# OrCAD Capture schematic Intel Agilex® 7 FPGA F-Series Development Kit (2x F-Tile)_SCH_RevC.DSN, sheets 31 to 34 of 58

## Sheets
31 PG34 CXL CONNECTOR: size C
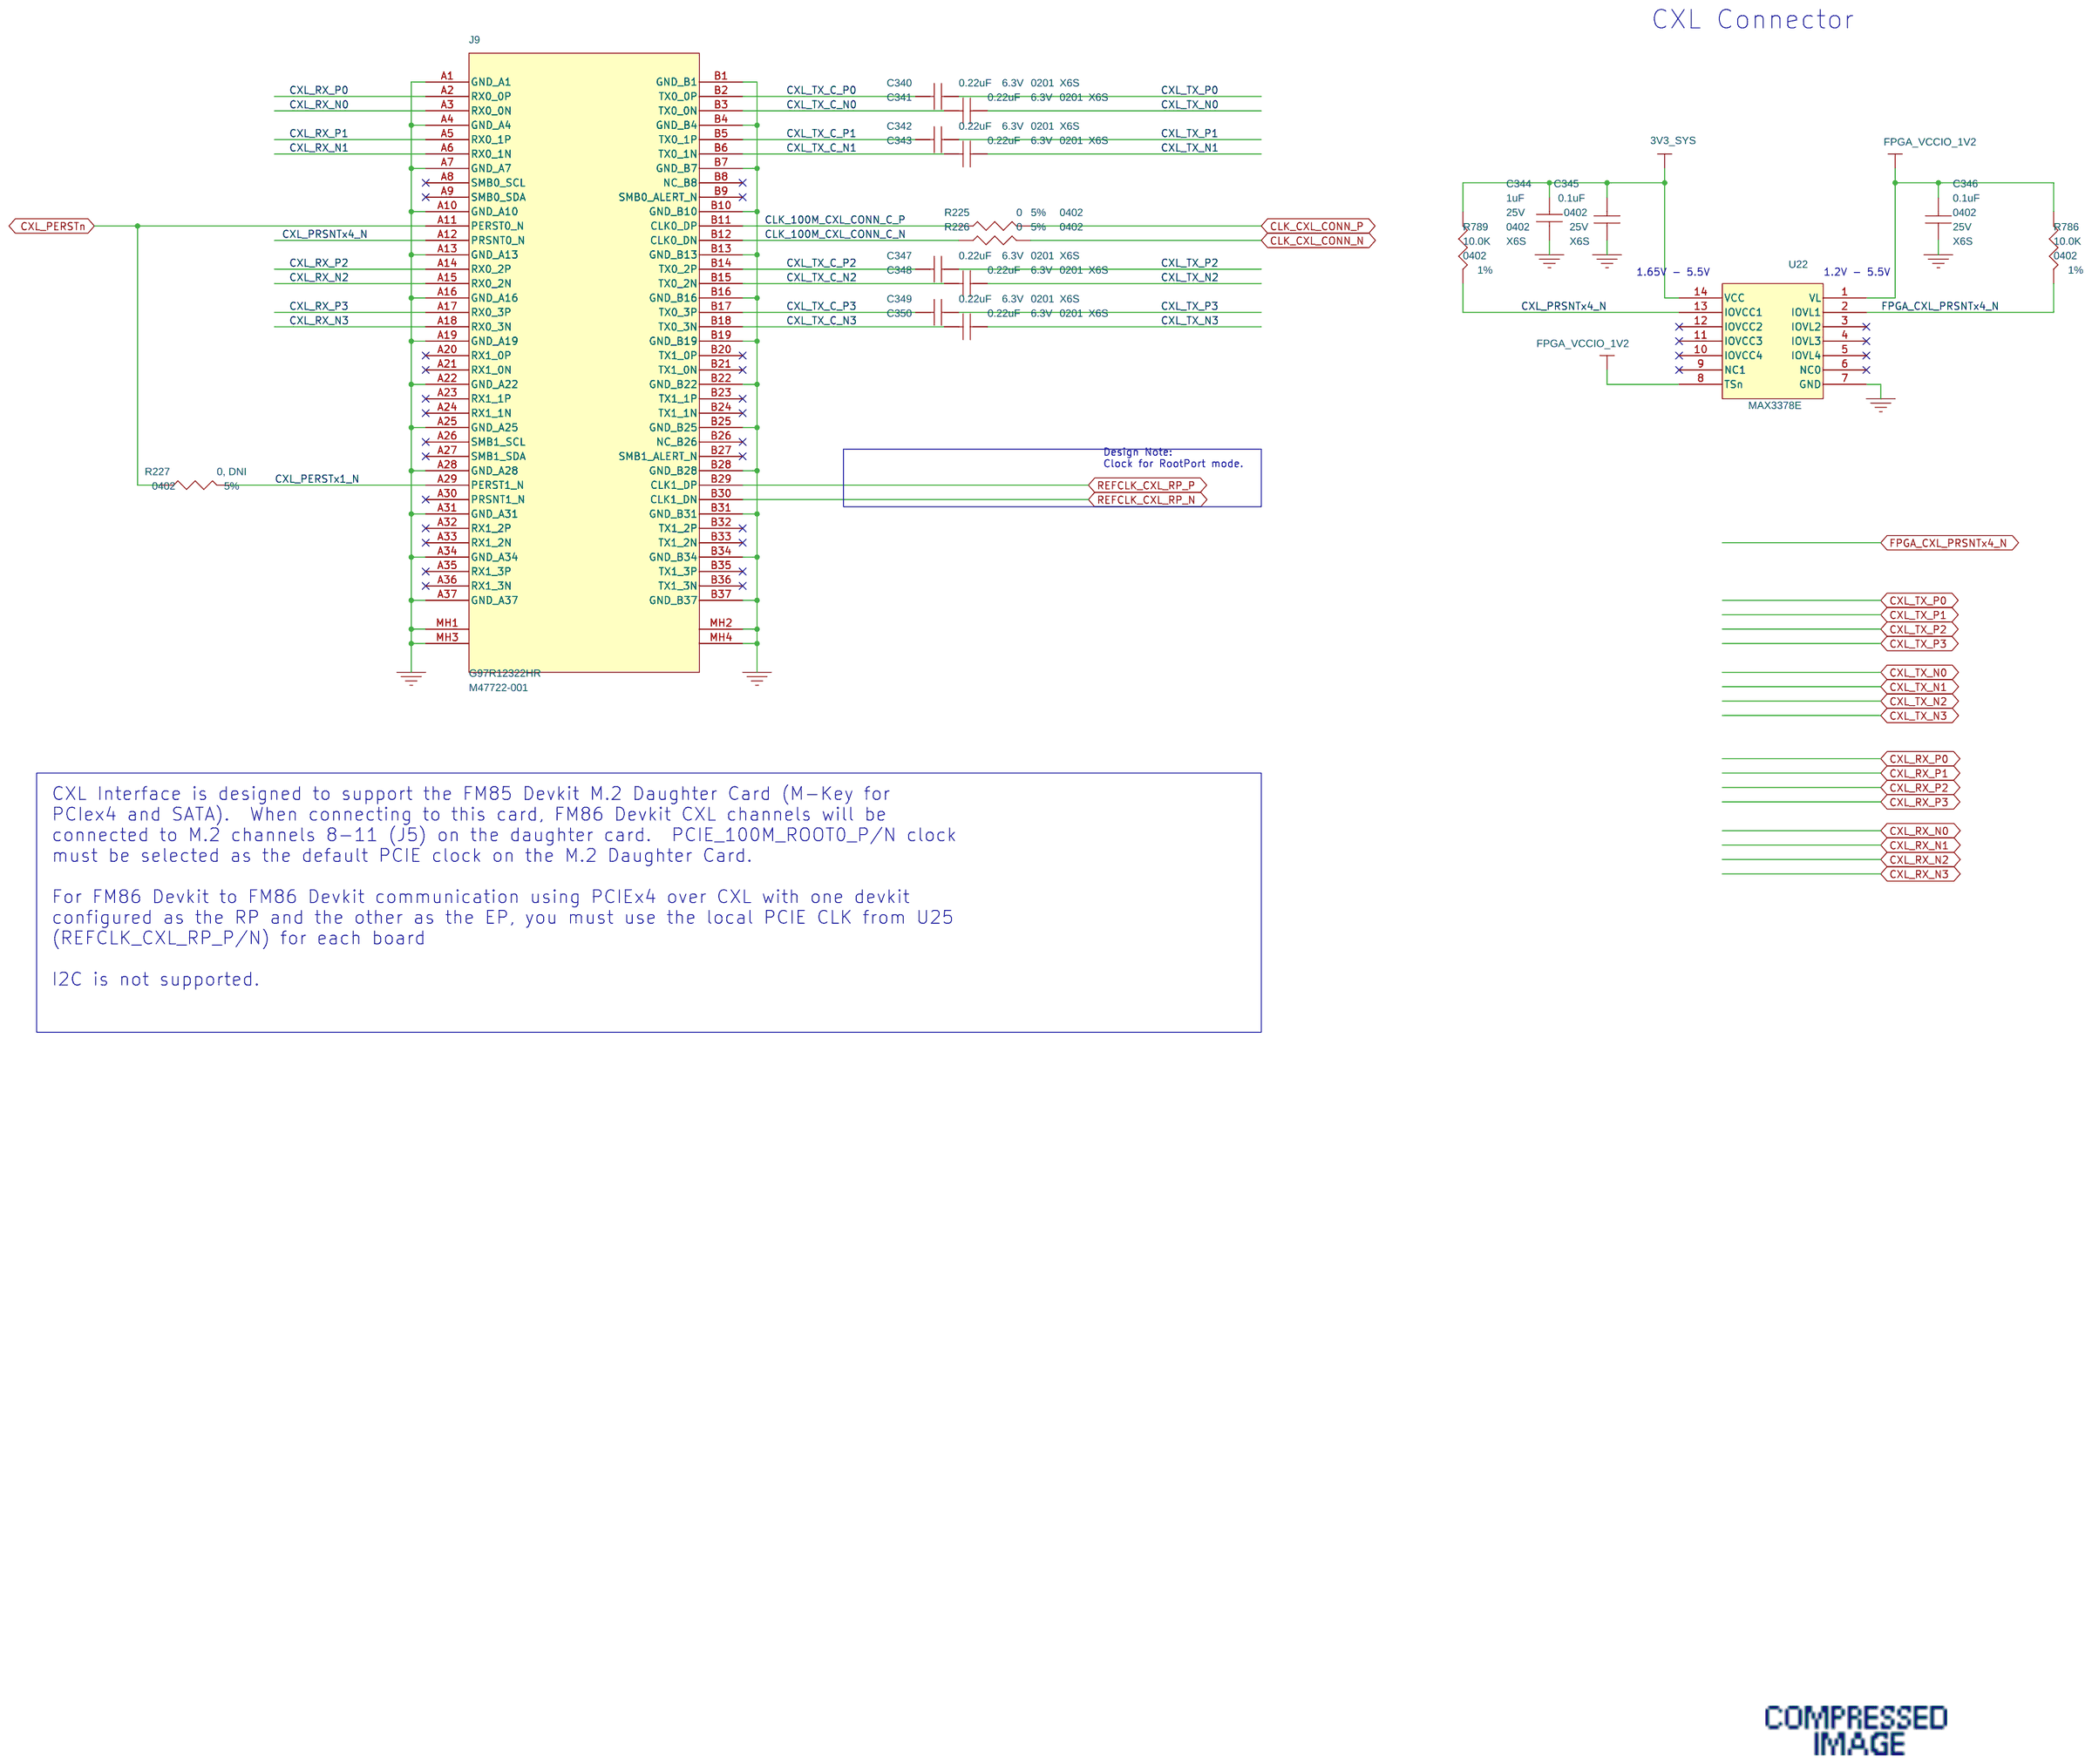
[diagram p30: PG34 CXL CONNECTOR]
32 PG35 CLOCK 1: size C
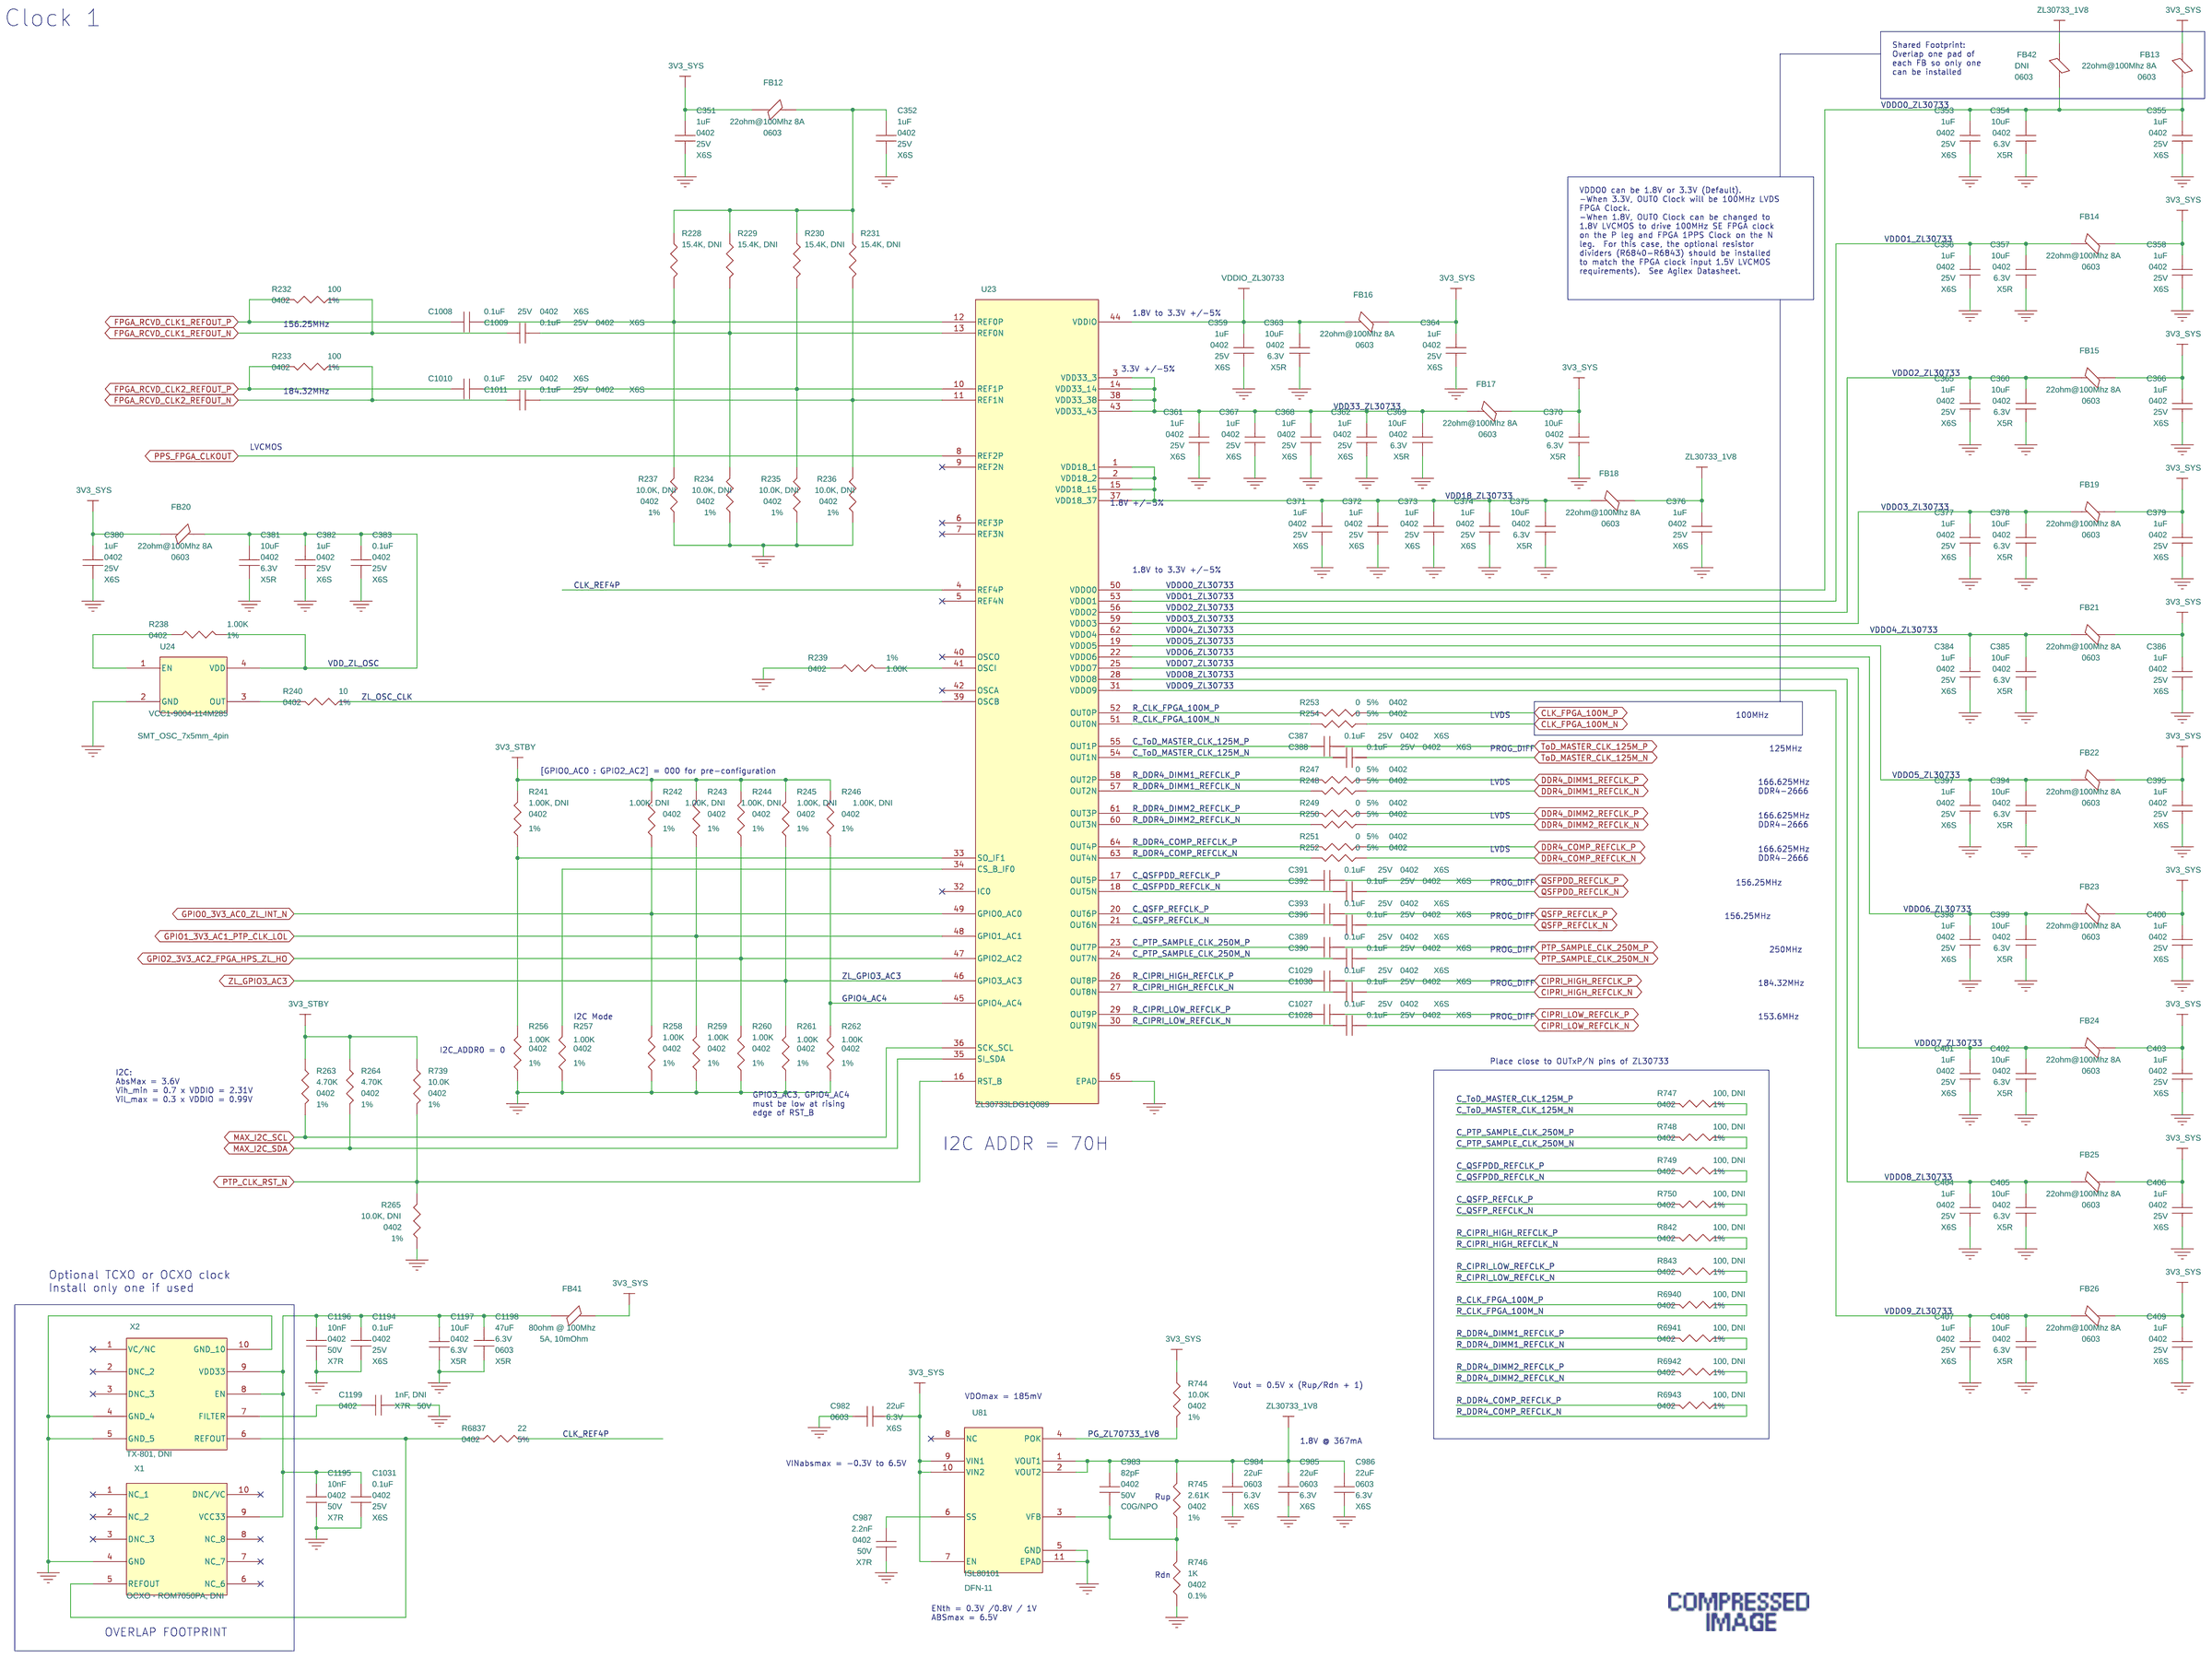
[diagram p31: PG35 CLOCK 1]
33 PG36 CLOCK 2: size C
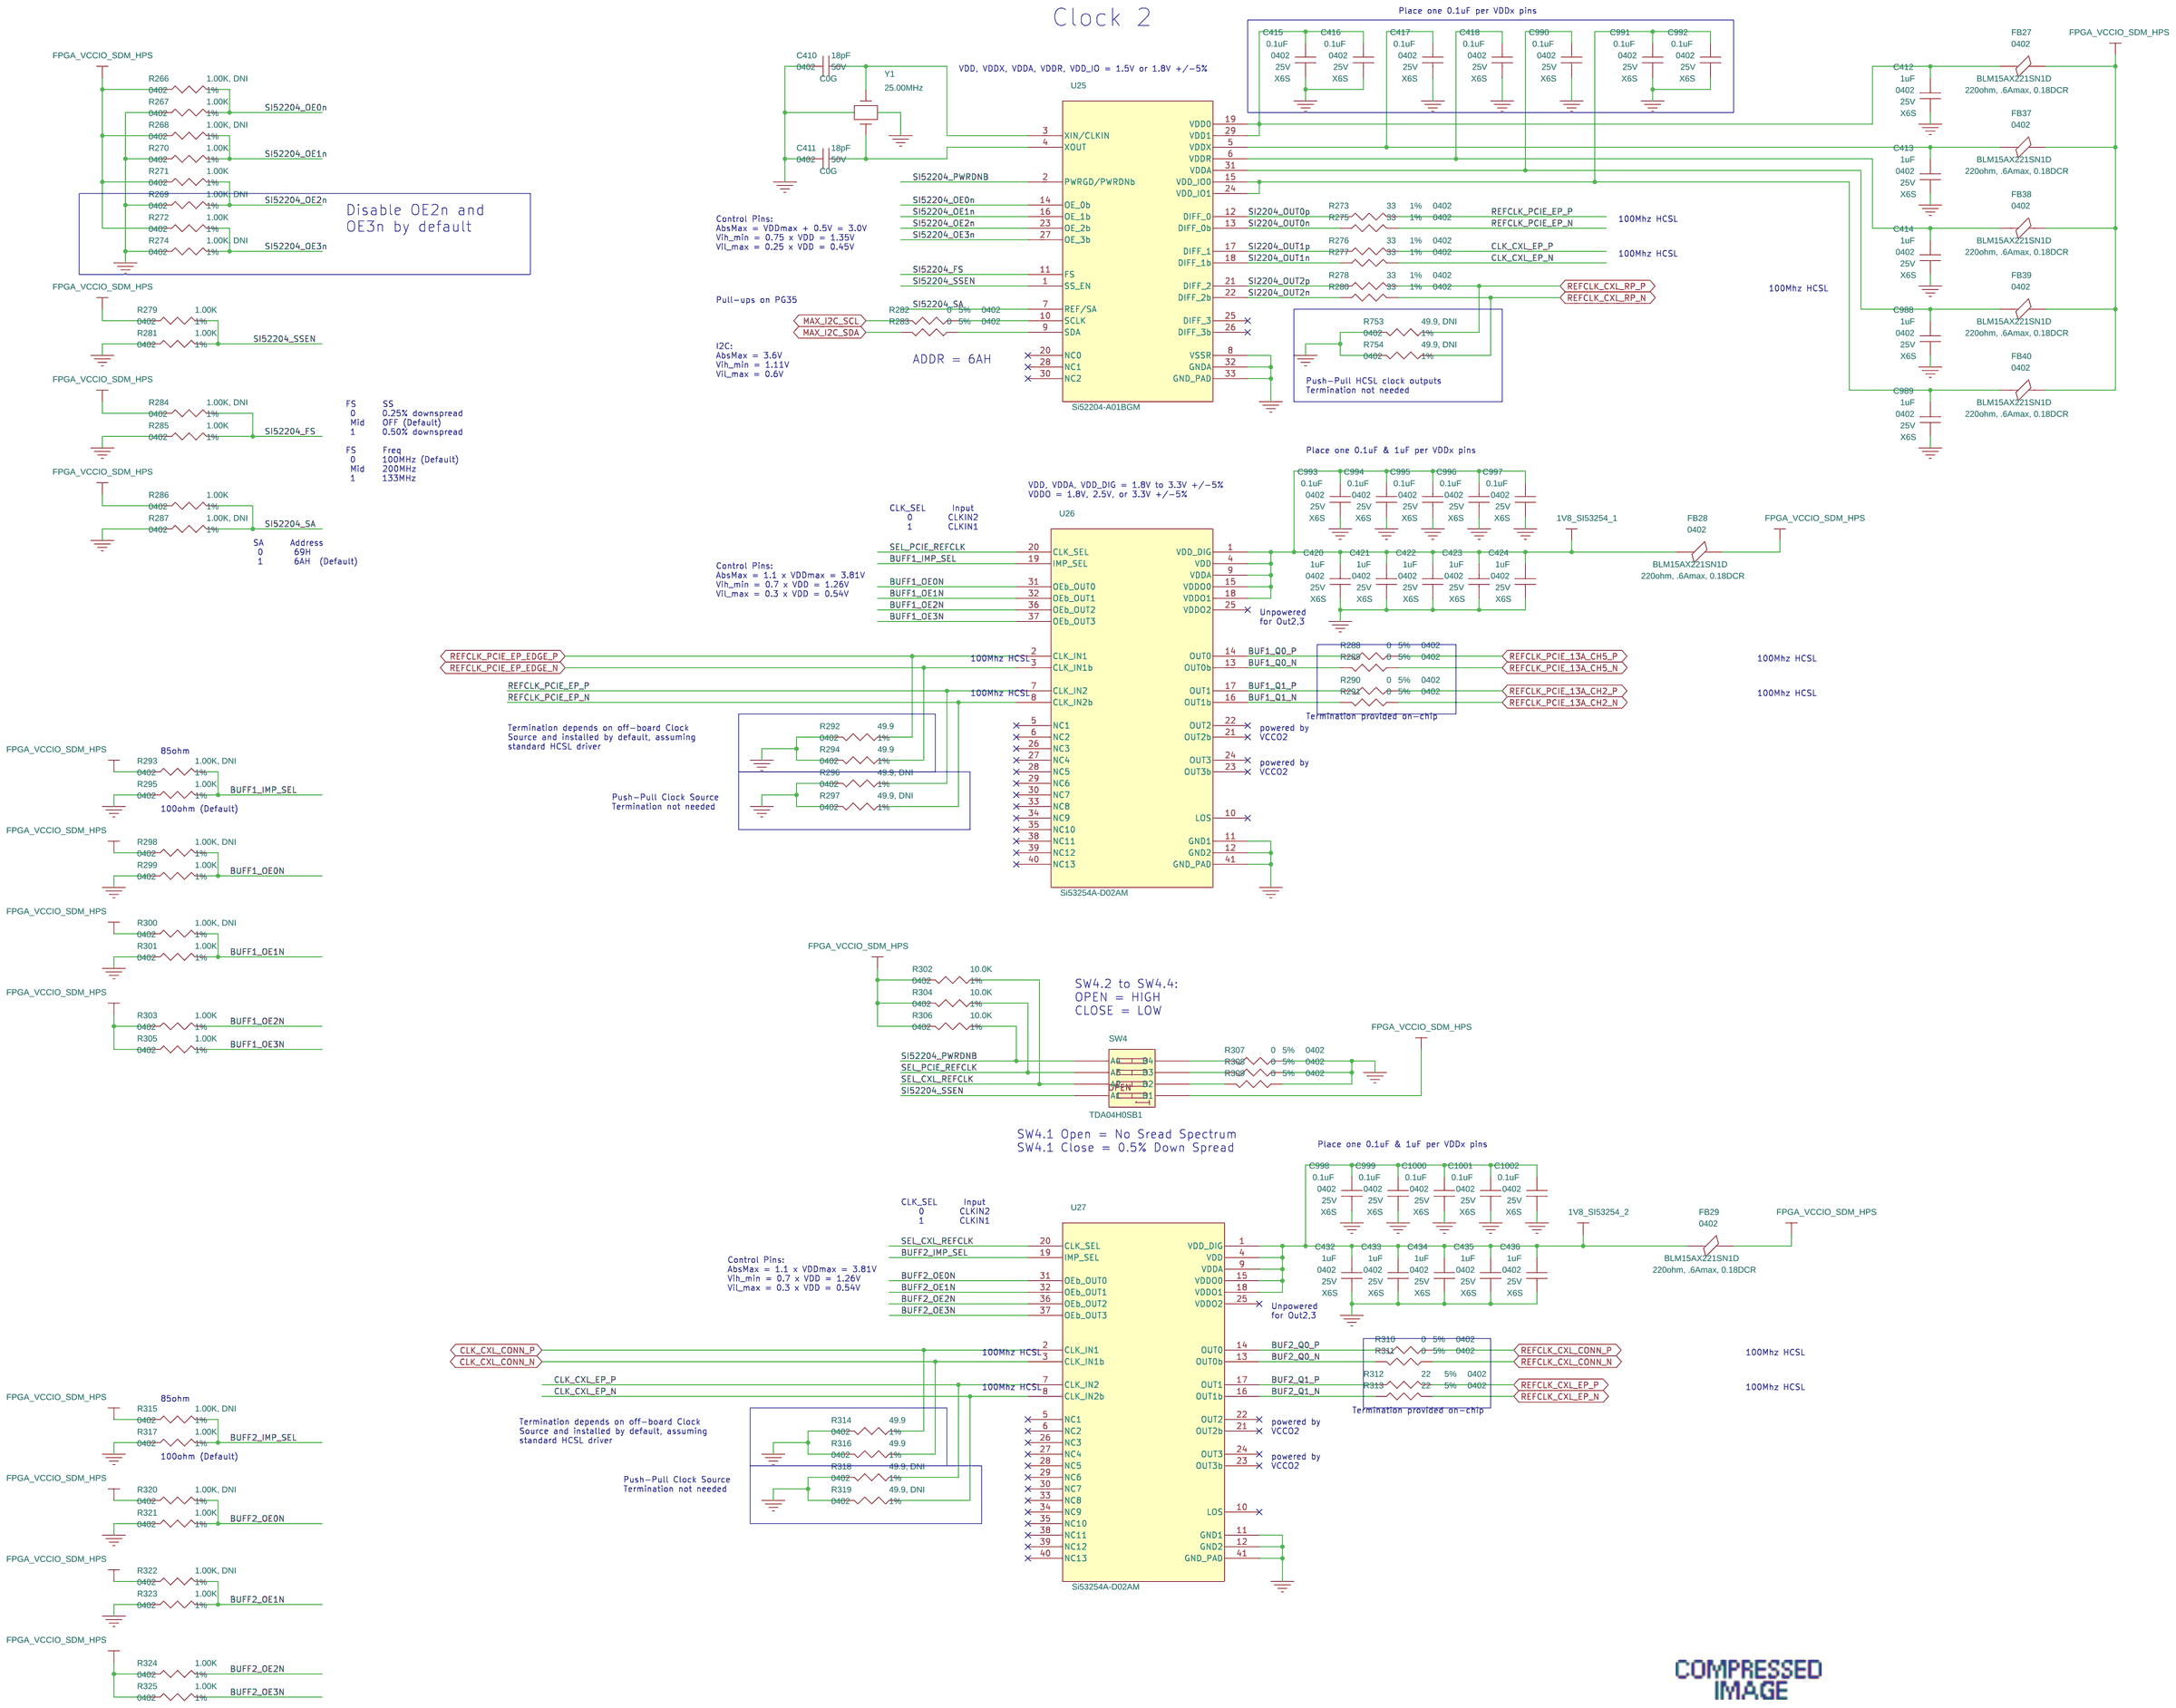
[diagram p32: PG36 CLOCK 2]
34 PG37 BUFFERS, TRANSLATORS: size C
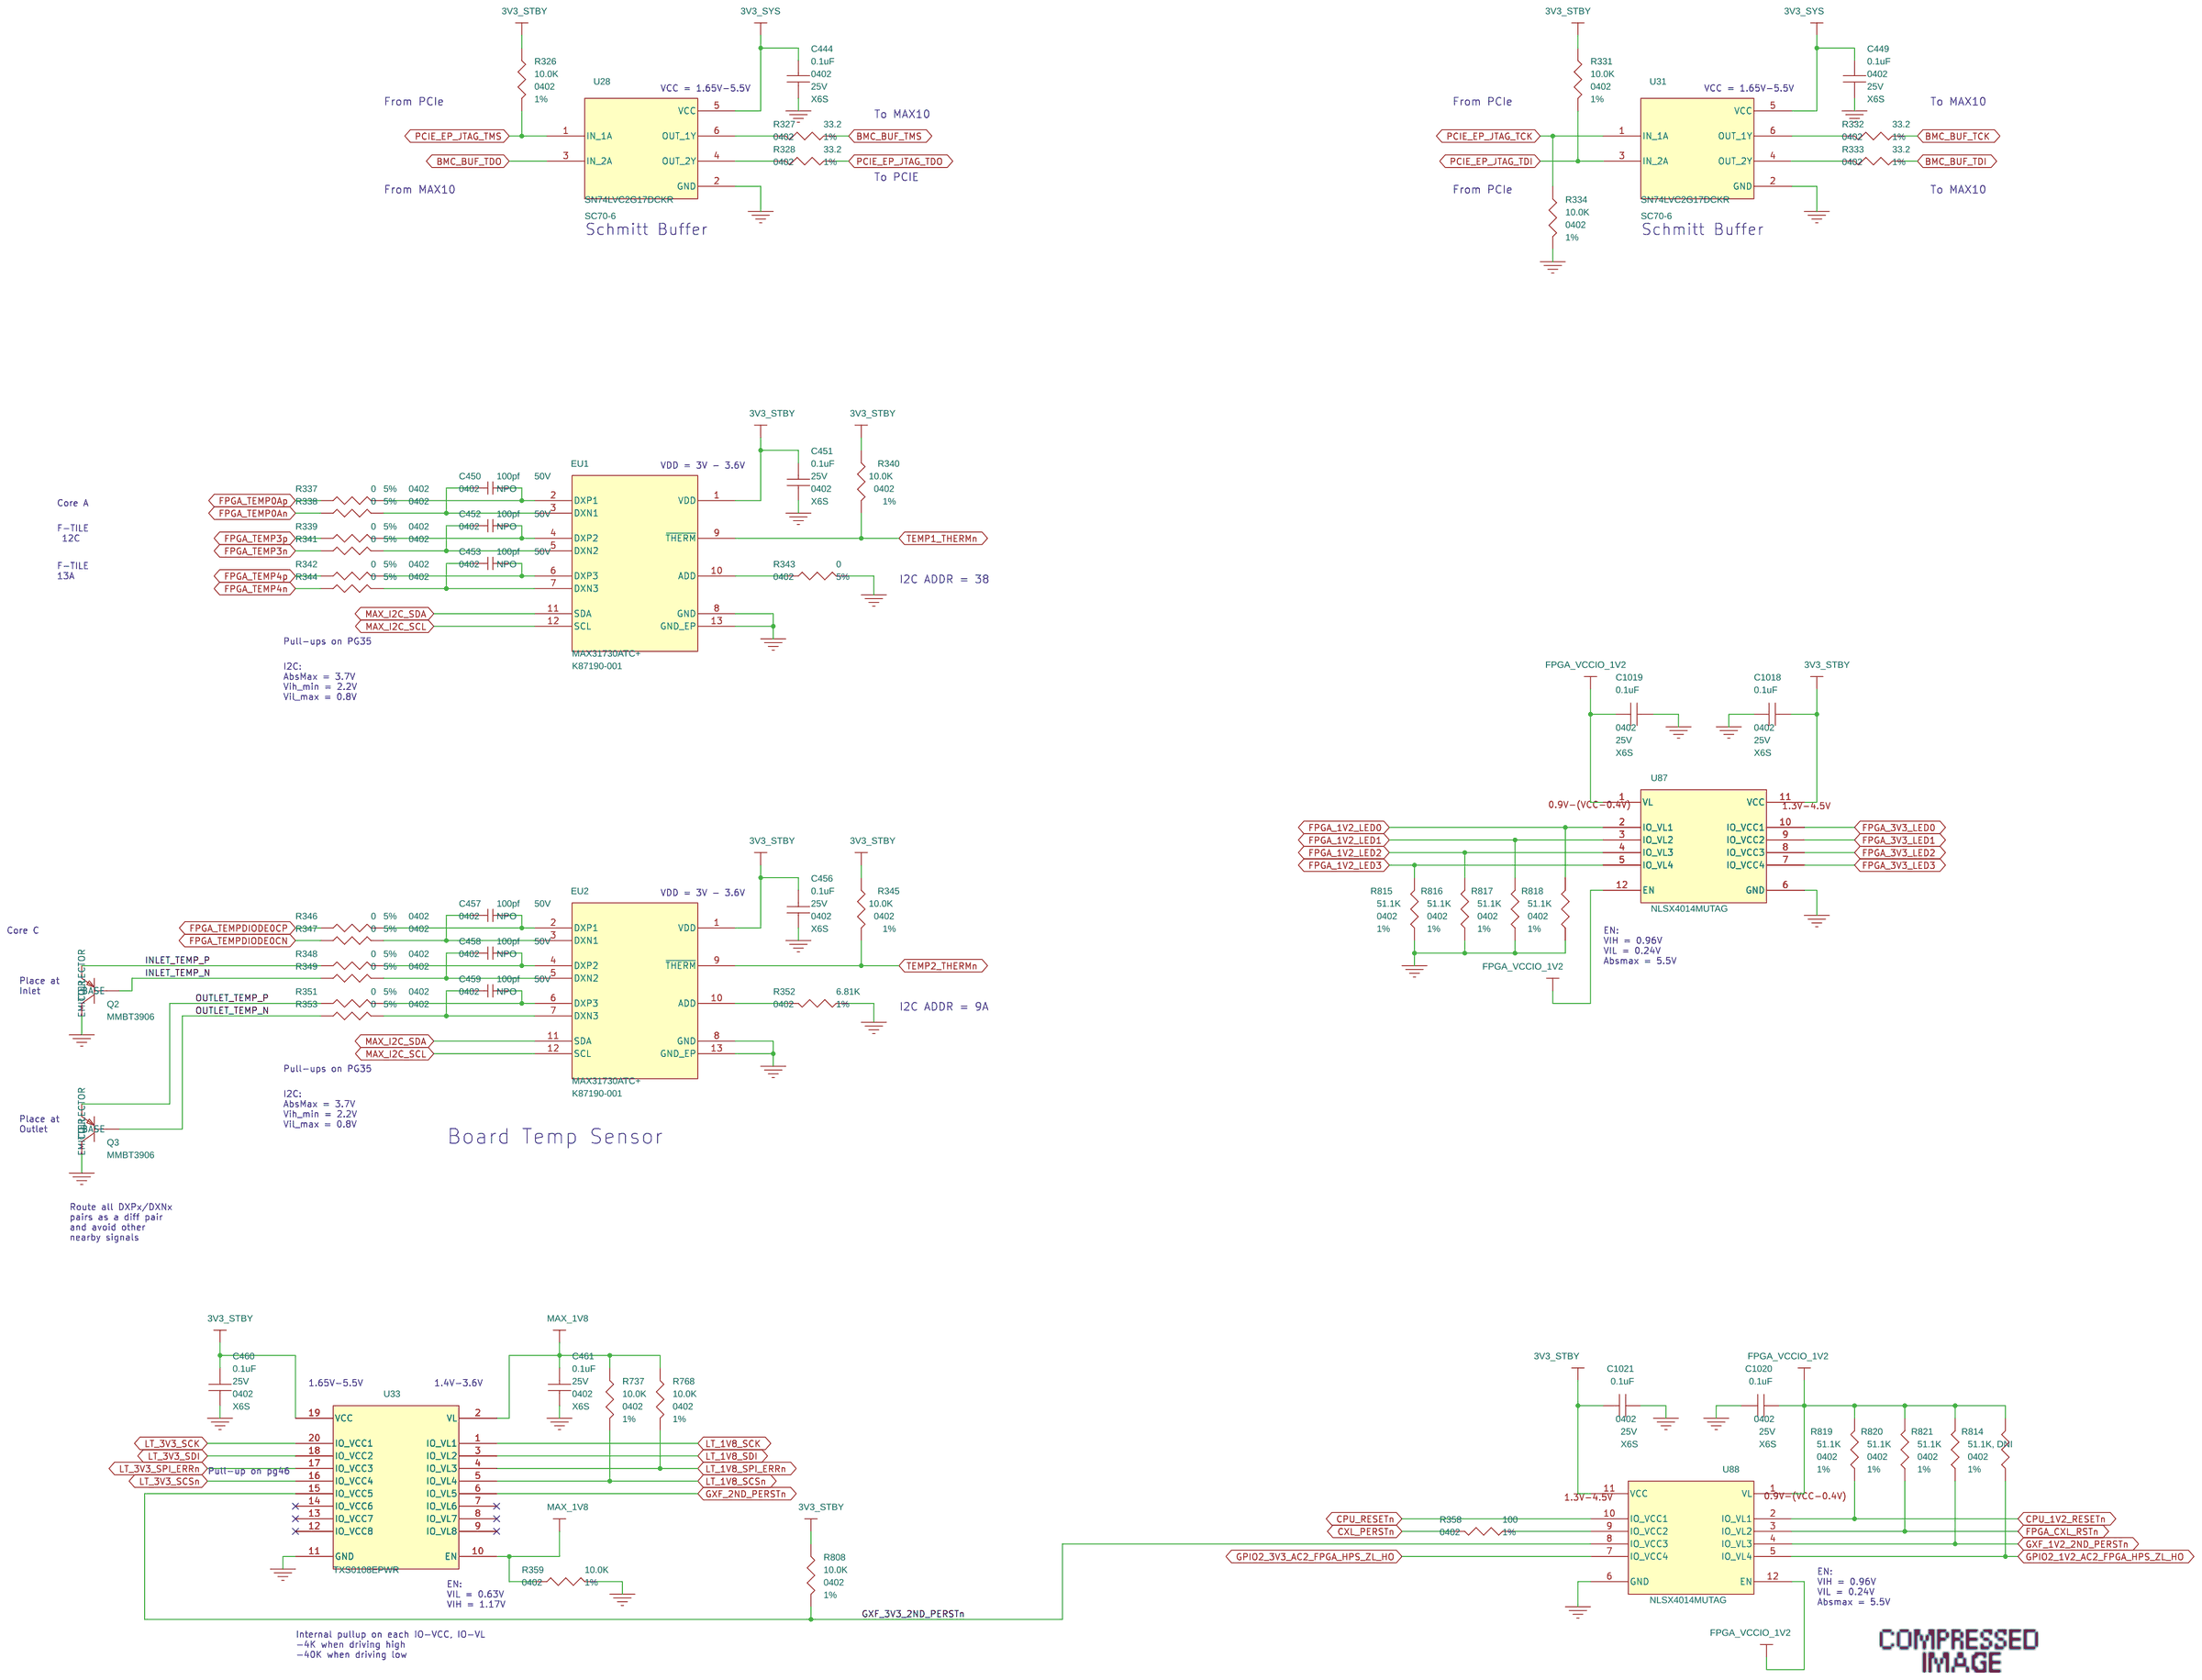
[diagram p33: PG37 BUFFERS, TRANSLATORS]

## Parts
sheet PG34 CXL CONNECTOR
C340  0.22uF  [SMC0201IA]
C341  0.22uF  [SMC0201IA]
C342  0.22uF  [SMC0201IA]
C343  0.22uF  [SMC0201IA]
C344  1uF  [0402]
C345  0.1uF  [0402]
C346  0.1uF  [0402]
C347  0.22uF  [SMC0201IA]
C348  0.22uF  [SMC0201IA]
C349  0.22uF  [SMC0201IA]
C350  0.22uF  [SMC0201IA]
J9  G97R12322HR  [G97R12322HR]
R225  0  [0402]
R226  0  [0402]
R227  0, DNI  [0402]
R786  10.0K  [0402]
R789  10.0K  [0402]
U22  MAX3378E  [TSSOP-14]
sheet PG35 CLOCK 1
C351  1uF  [0402]
C352  1uF  [0402]
C353  1uF  [0402]
C354  10uF  [0402]
C355  1uF  [0402]
C356  1uF  [0402]
C357  10uF  [0402]
C358  1uF  [0402]
C359  1uF  [0402]
C360  10uF  [0402]
C361  1uF  [0402]
C362  1uF  [0402]
C363  10uF  [0402]
C364  1uF  [0402]
C365  1uF  [0402]
C366  1uF  [0402]
C367  1uF  [0402]
C368  1uF  [0402]
C369  10uF  [0402]
C370  10uF  [0402]
C371  1uF  [0402]
C372  1uF  [0402]
C373  1uF  [0402]
C374  1uF  [0402]
C375  10uF  [0402]
C376  1uF  [0402]
C377  1uF  [0402]
C378  10uF  [0402]
C379  1uF  [0402]
C380  1uF  [0402]
C381  10uF  [0402]
C382  1uF  [0402]
C383  0.1uF  [0402]
C384  1uF  [0402]
C385  10uF  [0402]
C386  1uF  [0402]
C387  0.1uF  [0402]
C388  0.1uF  [0402]
C389  0.1uF  [0402]
C390  0.1uF  [0402]
C391  0.1uF  [0402]
C392  0.1uF  [0402]
C393  0.1uF  [0402]
C394  10uF  [0402]
C395  1uF  [0402]
C396  0.1uF  [0402]
C397  1uF  [0402]
C398  1uF  [0402]
C399  10uF  [0402]
C400  1uF  [0402]
C401  1uF  [0402]
C402  10uF  [0402]
C403  1uF  [0402]
C404  1uF  [0402]
C405  10uF  [0402]
C406  1uF  [0402]
C407  1uF  [0402]
C408  10uF  [0402]
C409  1uF  [0402]
C982  22uF  [0603]
C983  82pF  [0402]
C984  22uF  [0603]
C985  22uF  [0603]
C986  22uF  [0603]
C987  2.2nF  [0402]
C1008  0.1uF  [0402]
C1009  0.1uF  [0402]
C1010  0.1uF  [0402]
C1011  0.1uF  [0402]
C1027  0.1uF  [0402]
C1028  0.1uF  [0402]
C1029  0.1uF  [0402]
C1030  0.1uF  [0402]
C1031  0.1uF  [0402]
C1194  0.1uF  [0402]
C1195  10nF  [0402]
C1196  10nF  [0402]
C1197  10uF  [0402]
C1198  47uF  [0603]
C1199  1nF, DNI  [0402]
FB12  22ohm@100Mhz 8A  [0603]
FB13  22ohm@100Mhz 8A  [0603]
FB14  22ohm@100Mhz 8A  [0603]
FB15  22ohm@100Mhz 8A  [0603]
FB16  22ohm@100Mhz 8A  [0603]
FB17  22ohm@100Mhz 8A  [0603]
FB18  22ohm@100Mhz 8A  [0603]
FB19  22ohm@100Mhz 8A  [0603]
FB20  22ohm@100Mhz 8A  [0603]
FB21  22ohm@100Mhz 8A  [0603]
FB22  22ohm@100Mhz 8A  [0603]
FB23  22ohm@100Mhz 8A  [0603]
FB24  22ohm@100Mhz 8A  [0603]
FB25  22ohm@100Mhz 8A  [0603]
FB26  22ohm@100Mhz 8A  [0603]
FB41  80ohm @ 100Mhz  [0805]
FB42  DNI  [0603]
R228  15.4K, DNI  [HC_R0201]
R229  15.4K, DNI  [HC_R0201]
R230  15.4K, DNI  [HC_R0201]
R231  15.4K, DNI  [HC_R0201]
R232  100  [0402]
R233  100  [0402]
R234  10.0K, DNI  [0402]
R235  10.0K, DNI  [0402]
R236  10.0K, DNI  [0402]
R237  10.0K, DNI  [0402]
R238  1.00K  [0402]
R239  1.00K  [0402]
R240  10  [0402]
R241  1.00K, DNI  [0402]
R242  1.00K, DNI  [0402]
R243  1.00K, DNI  [0402]
R244  1.00K, DNI  [0402]
R245  1.00K, DNI  [0402]
R246  1.00K, DNI  [0402]
R247  0  [0402]
R248  0  [0402]
R249  0  [0402]
R250  0  [0402]
R251  0  [0402]
R252  0  [0402]
R253  0  [0402]
R254  0  [0402]
R256  1.00K  [0402]
R257  1.00K  [0402]
R258  1.00K  [0402]
R259  1.00K  [0402]
R260  1.00K  [0402]
R261  1.00K  [0402]
R262  1.00K  [0402]
R263  4.70K  [0402]
R264  4.70K  [0402]
R265  10.0K, DNI  [0402]
R739  10.0K  [0402]
R744  10.0K  [0402]
R745  2.61K  [0402]
R746  1K  [0402]
R747  100, DNI  [0402]
R748  100, DNI  [0402]
R749  100, DNI  [0402]
R750  100, DNI  [0402]
R842  100, DNI  [0402]
R843  100, DNI  [0402]
R6837  22  [0402]
R6940  100, DNI  [0402]
R6941  100, DNI  [0402]
R6942  100, DNI  [0402]
R6943  100, DNI  [0402]
U23  ZL30733LDG1Q089  [ZL30733]
U24  VCC1-9004-114M285  [SMT_OSC_7x5mm_4pin]
U81  ISL80101  [DFN-11]
X1  OCXO - ROM7050PA, DNI  [ROM7050PA]
X2  TX-801, DNI  [TX801_G320]
sheet PG36 CLOCK 2
C410  18pF  [0402]
C411  18pF  [0402]
C412  1uF  [0402]
C413  1uF  [0402]
C414  1uF  [0402]
C415  0.1uF  [0402]
C416  0.1uF  [0402]
C417  0.1uF  [0402]
C418  0.1uF  [0402]
C420  1uF  [0402]
C421  1uF  [0402]
C422  1uF  [0402]
C423  1uF  [0402]
C424  1uF  [0402]
C432  1uF  [0402]
C433  1uF  [0402]
C434  1uF  [0402]
C435  1uF  [0402]
C436  1uF  [0402]
C988  1uF  [0402]
C989  1uF  [0402]
C990  0.1uF  [0402]
C991  0.1uF  [0402]
C992  0.1uF  [0402]
C993  0.1uF  [0402]
C994  0.1uF  [0402]
C995  0.1uF  [0402]
C996  0.1uF  [0402]
C997  0.1uF  [0402]
C998  0.1uF  [0402]
C999  0.1uF  [0402]
C1000  0.1uF  [0402]
C1001  0.1uF  [0402]
C1002  0.1uF  [0402]
FB27  220ohm, .6Amax, 0.18DCR  [0402]
FB28  220ohm, .6Amax, 0.18DCR  [0402]
FB29  220ohm, .6Amax, 0.18DCR  [0402]
FB37  220ohm, .6Amax, 0.18DCR  [0402]
FB38  220ohm, .6Amax, 0.18DCR  [0402]
FB39  220ohm, .6Amax, 0.18DCR  [0402]
FB40  220ohm, .6Amax, 0.18DCR  [0402]
R266  1.00K, DNI  [0402]
R267  1.00K  [0402]
R268  1.00K, DNI  [0402]
R269  1.00K, DNI  [0402]
R270  1.00K  [0402]
R271  1.00K  [0402]
R272  1.00K  [0402]
R273  33  [0402]
R274  1.00K, DNI  [0402]
R275  33  [0402]
R276  33  [0402]
R277  33  [0402]
R278  33  [0402]
R279  1.00K  [0402]
R280  33  [0402]
R281  1.00K  [0402]
R282  0  [0402]
R283  0  [0402]
R284  1.00K, DNI  [0402]
R285  1.00K  [0402]
R286  1.00K  [0402]
R287  1.00K, DNI  [0402]
R288  0  [0402]
R289  0  [0402]
R290  0  [0402]
R291  0  [0402]
R292  49.9  [0402]
R293  1.00K, DNI  [0402]
R294  49.9  [0402]
R295  1.00K  [0402]
R296  49.9, DNI  [0402]
R297  49.9, DNI  [0402]
R298  1.00K, DNI  [0402]
R299  1.00K  [0402]
R300  1.00K, DNI  [0402]
R301  1.00K  [0402]
R302  10.0K  [0402]
R303  1.00K  [0402]
R304  10.0K  [0402]
R305  1.00K  [0402]
R306  10.0K  [0402]
R307  0  [0402]
R308  0  [0402]
R309  0  [0402]
R310  0  [0402]
R311  0  [0402]
R312  22  [0402]
R313  22  [0402]
R314  49.9  [0402]
R315  1.00K, DNI  [0402]
R316  49.9  [0402]
R317  1.00K  [0402]
R318  49.9, DNI  [0402]
R319  49.9, DNI  [0402]
R320  1.00K, DNI  [0402]
R321  1.00K  [0402]
R322  1.00K, DNI  [0402]
R323  1.00K  [0402]
R324  1.00K  [0402]
R325  1.00K  [0402]
R753  49.9, DNI  [0402]
R754  49.9, DNI  [0402]
SW4  TDA04H0SB1  [DIPSWITCH_SMT_QUAD]
U25  Si52204-A01BGM  [QFN32L]
U26  Si53254A-D02AM  [SI53254_QFN40]
U27  Si53254A-D02AM  [SI53254_QFN40]
Y1  25.00MHz  [XTAL_FA-128]
sheet PG37 BUFFERS, TRANSLATORS
C444  0.1uF  [0402]
C449  0.1uF  [0402]
C450  100pf  [0402]
C451  0.1uF  [0402]
C452  100pf  [0402]
C453  100pf  [0402]
C456  0.1uF  [0402]
C457  100pf  [0402]
C458  100pf  [0402]
C459  100pf  [0402]
C460  0.1uF  [0402]
C461  0.1uF  [0402]
C1018  0.1uF  [0402]
C1019  0.1uF  [0402]
C1020  0.1uF  [0402]
C1021  0.1uF  [0402]
EU1  MAX31730ATC+  [lcc12_s30_50df25x17ma]
EU2  MAX31730ATC+  [lcc12_s30_50df25x17ma]
Q2  MMBT3906  [SC75_SOT416]
Q3  MMBT3906  [SC75_SOT416]
R326  10.0K  [0402]
R327  33.2  [0402]
R328  33.2  [0402]
R331  10.0K  [0402]
R332  33.2  [0402]
R333  33.2  [0402]
R334  10.0K  [0402]
R337  0  [0402]
R338  0  [0402]
R339  0  [0402]
R340  10.0K  [0402]
R341  0  [0402]
R342  0  [0402]
R343  0  [0402]
R344  0  [0402]
R345  10.0K  [0402]
R346  0  [0402]
R347  0  [0402]
R348  0  [0402]
R349  0  [0402]
R351  0  [0402]
R352  6.81K  [0402]
R353  0  [0402]
R358  100  [0402]
R359  10.0K  [0402]
R737  10.0K  [0402]
R768  10.0K  [0402]
R808  10.0K  [0402]
R814  51.1K, DNI  [0402]
R815  51.1K  [0402]
R816  51.1K  [0402]
R817  51.1K  [0402]
R818  51.1K  [0402]
R819  51.1K  [0402]
R820  51.1K  [0402]
R821  51.1K  [0402]
U28  SN74LVC2G17DCKR  [SC70-6]
U31  SN74LVC2G17DCKR  [SC70-6]
U33  TXS0108EPWR  [20-TSSOP]
U87  NLSX4014MUTAG  [UQFN12]
U88  NLSX4014MUTAG  [UQFN12]

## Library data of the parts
C340-C343 C347-C350 = CAP: CAP - CER, 0.22UF, 6.3V, 10%, X6S, 0201; Item Num: J19343-004; Manufacturer: Murata; Manufacturer Part Num: GRM033C80J224KE90D; Num Pins: 2; PART_SUBCLASS: CAPACITORS; Package: 0201; RATED_VOLTAGE: 6.3V; TOLERANCE: +/-10%; Temperature Coefficient: X6S
C344 = CAP: CAP CER 1UF 25V X6S 0402; Item Num: H81594-001; Lead Free Status: Yes; Manufacturer: Murata; Manufacturer Part Num: GRM155C81E105KE11D; Num Pins: 2; Part Class: CAPACITORS; RATED_VOLTAGE: 25V; RoHS Compliant: Yes; Temperature Coefficient: X6S; Voltage: 25V
C345 C346 C383 C415-C418 C444 C449 C451 C456 C460 C461 C990-C1002 C1018-C1021 C1031 C1194 = CAP: CAP CER 0.1UF 25V X6S 0402; Dielectric: X6S; IPN: K19434-001; Item Num: K19434-001; LIFECYCLE_PHASE: Active; Lead Free Status: Lead Free; MFR_LIFECYCLE: Active; Manufacturer: Murata; Manufacturer Part Num: GRM155C81E104KA12D; Num Pins: 2; PART_SUBCLASS: CAPACITORS; Part Class: CAPACITORS; RATED_VOLTAGE: 25V; RoHS Compliant: RoHS Compliant; Temperature Coefficient: X6S; Tolerance: 10%
J9 = CON_MCIO_74P_G42V12312HR: MCIO x8 Conn, 74p, G97R12322HR; IPN: M47722-001; Item Num: M47722-001; Manufacturer: Amphenol
R225 R226 = RESISTOR: RES ZERO OHM 1/16W 5% 0402 SMD; Agile IPN: P02-14020R; IPN: A93549-001; Item Num: A93549-001; Manufacturer: Yageo; Manufacturer Part Num: RC0402JR-070RL; Num Pins: 2; Part Class: RESISTORS; Tolerance: 5%
R227 = RESISTOR: RES ZERO OHM 1/16W 5% 0402 SMD; IPN: A93549-001; Item Num: A93549-001; Lead Free Status: Yes; Manufacturer: Yageo; Manufacturer Part Num: RC0402JR-070RL; Num Pins: 2; Part Class: RESISTORS; RoHS Compliant: Yes; Tolerance: 5%
R302 R304 R306 R326 R331 R334 R340 R345 R359 R737 R739 R744 R768 R786 R789 R808 = RESISTOR: RES,10.0K OHMS,1.0%,1/16W, 0402; AGILE_LINK: http://sj-agile9app/Agile/PLMServlet?action=OpenEmailObject&classid=10000&objid=146548997; Item Num: K28115-001; LIFECYCLE_PHASE: Active; Lead Free Status: Yes; MFR_LIFECYCLE: Active; Manufacturer: Panasonic; Manufacturer Part Num: ERJ-2RKF1002X; Num Pins: 2; PART_SUBCLASS: RESISTORS; POWER: 1/16W; RoHS Compliant: Yes; TOLERANCE: 1%
U22 = MAX3378E_0: IC - QUAD LOW-VOLTAGE LEVEL TRANSLATOR, +/- 15KV, ESD-PROTECTED, 1UA, 16MBPS; Item Num: C34337-001; Manufacturer: Maxim; Manufacturer Part Num: MAX3378EEUD
C351-C353 C355 C356 C358 C359 C361 C362 C364-C368 C371-C374 C376 C377 C379 C380 C382 C384 C386 C395 C397 C398 C400 C401 C403 C404 C406 C407 C409 C412-C414 C420-C424 C432-C436 C988 C989 = CAP: CAP CER 1UF 25V X6S 0402; Item Num: H81594-001; Lead Free Status: Yes; Manufacturer: Murata; Manufacturer Part Num: GRM155C81E105KE11D; Num Pins: 2; Part Class: CAPACITORS; RATED_VOLTAGE: 25V; RoHS Compliant: Yes; Temperature Coefficient: X6S
C354 C357 C360 C363 C369 C370 C375 C378 C381 C385 C394 C399 C402 C405 C408 C1197 = CAP: CAP CER 10UF 6.3V X5R 0402; AGILE_LINK: http://sj-agile9app/Agile/PLMServlet?action=OpenEmailObject&classid=10000&objid=257560276; Item Num: K46607-001; LIFECYCLE_PHASE: Active; Lead Free Status: Lead Free; MFR_LIFECYCLE: Active; Manufacturer: Murata Electronics North America; Manufacturer Part Num: GRJ155R60J106ME11D; Num Pins: 2; PART_SUBCLASS: CAPACITORS; Part Class: CAPACITORS; RATED_VOLTAGE: 6.3V; RoHS Compliant: RoHS Compliant; TOLERANCE: 20%; Temperature Coefficient: X5R
C387-C393 C396 C1008-C1011 C1027-C1030 = CAP: CAP CER 0.1UF 25V X6S 0402; Dielectric: X6S; IPN: K19434-001; Item Num: K19434-001; LIFECYCLE_PHASE: Active; Lead Free Status: Lead Free; MFR_LIFECYCLE: Active; Manufacturer: Murata; Manufacturer Part Num: GRM155C81E104KA12D; Num Pins: 2; PART_SUBCLASS: CAPACITORS; Part Class: CAPACITORS; RATED_VOLTAGE: 25V; RoHS Compliant: RoHS Compliant; Temperature Coefficient: X6S; Tolerance: 10%; Voltage: <Voltage>
C982 C984-C986 = CAP: CAP CER 22UF 6.3V X6S 0603; AGILE_LINK: http://sj-agile9app/Agile/PLMServlet?action=OpenEmailObject&classid=10000&objid=257560276; Item Num: H63299-001; LIFECYCLE_PHASE: Active; Lead Free Status: Not Lead Free; MFR_LIFECYCLE: Active; Manufacturer: Murata; Manufacturer Part Num: GRM188C80J226ME15D; Num Pins: 2; PART_SUBCLASS: CAPACITORS; RATED_VOLTAGE: 6.3V; RoHS Compliant: RoHS Compliant; TOLERANCE: 20%; Temperature Coefficient: X6S
C983 = CAP: CAP CER 82PF 50V C0G/NPO 0402; Dielectric: C0G/NPO; Item Num: K13615-001; Lead Free Status: Yes; Manufacturer: Yageo; Manufacturer Part Num: CC0402JRNPO9BN820; Num Pins: 2; Part Class: CAPACITORS; RoHS Compliant: Yes; Temperature Coefficient: C0G/NPO; Tolerance: 5%; Voltage Rating: 50V
C987 = CAP: CAP CER 2200PF 50V 10% X7R 0402; CAPACITANCE: 2200pF; Dielectric: X7R; Item Num: K13631-001; LIFECYCLE_PHASE: Active; Lead Free Status: Lead Free; Manufacturer: TDK; Manufacturer Part Num: CGJ2B2X7R1E222K050BA; Num Pins: 2; PART_SUBCLASS: CAPACITORS; Part Class: CAPACITORS; RATED_VOLTAGE: 50V; RoHS Compliant: RoHS Compliant; Temperature Coefficient: X7R; Tolerance: +/-10%
C1195 C1196 = Cap_10000PF_50V_0402: CAP - CER, 10NF, 50V, +/-10%, X7R, 0402 SMD; Dielectric: X7R; Item Num: H61346-001; LIFECYCLE_PHASE: Active; Lead Free Status: Lead Free; Manufacturer Part Num: GRM155R71H103KA88D; Num Pins: 2; Part Class: CAPACITORS; RATED_VOLTAGE: 50V; RoHS Compliant: RoHS Compliant; Temperature Coefficient: X7R; Tolerance: 10%; Voltage: 50V
C1198 = CAP: CAP CER 47UF 6.3V X5R 0603; IPN: 602433-109; Item Num: K31624-001; MFR_LIFECYCLE: Active; Manufacturer: Murata Electronics North America; Manufacturer Part Num: GRM188R60J476ME15D; Num Pins: 2; PART_SUBCLASS: CAPACITORS; RATED_VOLTAGE: 6.3V; RoHS Compliant: RoHS Compliant; TOLERANCE: 20%; Temperature Coefficient: X5R
C1199 = Cap_10000PF_50V_0402: CAP CER 1000PF 50V X7R 0402; Item Num: C20831-001; Manufacturer: Panasonic; Manufacturer Part Num: ECJ-0EB1H102K; Temp Coefficient: X7R; Working Voltage: 50V
FB12-FB26 FB42 = BEAD_FERRITE_SM: FERRITE BEAD 22 OHM 0603; Item Num: M16845-001; LIFECYCLE_PHASE: Active; MFR_LIFECYCLE: Active; Manufacturer: Murata; Manufacturer Part Num: BLM18SN220TZ1D; Num Pins: 2; PART_SUBCLASS: INDUCTORS; Part Class: Inductors; RoHS Compliant: Yes
FB41 = BEAD_FERRITE_SM: FERRITE BEAD 80 OHM 0805 1LN; Item Num: K75334-001; LIFECYCLE_PHASE: Active; MFR_LIFECYCLE: Active; Manufacturer: Laird; Manufacturer Part Num: HI0805R800R-10; Num Pins: 2; PART_SUBCLASS: INDUCTORS; Part Class: Inductors; RoHS Compliant: Yes; Value2: 5A, 10mOhm
R228-R231 = RES_VERT_HORIZ: RES SMD 15.4K OHM 1% 1/20W 0201; Item Num: C48657-449; Lifecycle: Production; Manufacturer: Yageo; Manufacturer Part Num: RC0201FR-0715K4L; Package: 0201; Speed Part Number: C48657-449; Tolerance: 1%
R232 R233 R358 R747-R750 R842 R843 R6940-R6943 = RESISTOR: RES,100 OHMS,1.0%,1/16W,0402; Item Num: A36092-043; Lead Free Status: Yes; Manufacturer: Yageo; Manufacturer Part Num: RC0402FR-07100RL; Num Pins: 2; Part Class: Resistors; Price: 0; RoHS Compliant: Yes; Tolerance: 1%
R234-R237 R265 = RESISTOR: RES,10.0K OHMS,1.0%,1/16W, 0402; AGILE_LINK: http://sj-agile9app/Agile/PLMServlet?action=OpenEmailObject&classid=10000&objid=146548997; Item Num: K28115-001; LIFECYCLE_PHASE: Active; Lead Free Status: Yes; MFR_LIFECYCLE: Active; Manufacturer: Panasonic; Manufacturer Part Num: ERJ-2RKF1002X; Num Pins: 2; PART_SUBCLASS: RESISTORS; POWER: 1/16W; RESISTANCE: 10.0K; RoHS Compliant: Yes; TOLERANCE: 1%
R238 R239 R241-R246 R256-R262 = RESISTOR: RES,1.00K OHMS,1.0%,1/16W,0402; Item Num: G60609-021; Lead Free Status: Yes; Manufacturer: Panasonic; Manufacturer Part Num: ERJ-2RKF1001X; Num Pins: 2; Part Class: Resistors; TOLERANCE: 1%
R240 = RESISTOR: RES, 10 OHM, 1%, 1/16W, 0402; Item Num: A80345-001; LIFECYCLE_PHASE: Active; Lead Free Status: Yes; Manufacturer: Panasonic; Manufacturer Part Num: ERJ-2RKF10R0X; Num Pins: 2; PART_SUBCLASS: RESISTORS; POWER: 1/16W; Part Class: Resistors; RoHS Compliant: Yes; TOLERANCE: 1%
R247-R254 R288-R291 R307-R311 = RES_0_OHM_5%_1_16W_0402_SMD: Item Num: A93549-001; Manufacturer: Yageo; Manufacturer Part Num: RC0402JR-070RL; Num Pins: 2; RoHS Compliant: Yes; Tolerance: 5%
R263 R264 = RESISTOR: RES,4.70K OHMS,1.0%,1/16W,0402; AGILE_LINK: http://sj-agile9app/Agile/PLMServlet?action=OpenEmailObject&classid=10000&objid=146753272; Item Num: A93548-517; LIFECYCLE_PHASE: Active; Lead Free Status: Yes; MFR_LIFECYCLE: Active; Manufacturer: Vishay; Manufacturer Part Num: CRCW04024K70FKED; Num Pins: 2; PART_SUBCLASS: RESISTORS; POWER: 1/16W; RESISTANCE: 4.7K; RoHS Compliant: Yes; TOLERANCE: 1%
R745 = RESISTOR: RES SMD 2.61K 1% 1/16W 0402; Item Num: A93548-419; Lead Free Status: Yes; Manufacturer: RC0402FR-072K61L; Manufaturer: Yageo; Num Pins: 2; Part Class: RESISTORS; RoHS Compliant: Yes; TOLERANCE: 1%
R746 = RESISTOR: RES SMD 1K OHM 0.1% 1/16W 0402; Item Num: K21643-001; Lead Free Status: Yes; Manufacturer: Panasonic; Manufacturer Part Num: ERA-2AEB102X; Num Pins: 2; Part Class: Resistors; Power Rating: 1/16W; RoHS Compliant: Yes; TOLERANCE: 0.1%
R312 R313 R6837 = RESISTOR: RES, 22 OHMS, 5%, 1/16W, 0402; AGILE_LINK: http://sj-agile9app/Agile/PLMServlet?action=OpenEmailObject&classid=10000&objid=218074840; Item Num: K15613-001; LIFECYCLE_PHASE: Active; MFR_LIFECYCLE: Active; Manufacturer: NIC Components Corp.; Manufacturer Part Num: NRC04J220TRF; Num Pins: 2; PART_SUBCLASS: RESISTORS; POWER: 1/16W; RoHS Compliant: RoHS Compliant; TOLERANCE: 5%
U23 = ZL30733: IC,CLK_DRVR,64QFN,N/A,SYNTH,PLL,; Item Num: M41980-001; Manufacturer: Microchip
U24 = SiLabs_510GBA25M0000BAGR: IC, Crystal Oscillator 114.285MHz; Item Num: A93546-085; Manufacturer: Vectron
U81 = EY1501di-adj: IC, Linear Regulator, 1A; Item Num: E81353-001; Manufacturer: Intel/Enpirion; Manufacturer Part Num: EY1501DI-ADJ
X1 = ROM7050PA
X2 = TX-801
C410 C411 = CAP: CAP - CERAMIC, 18PF, 5%, 50V, 0402, COG; AGILE_LINK: http://sj-agile9app/Agile/PLMServlet?action=OpenEmailObject&classid=10000&objid=213459014; Item Num: E60713-001; Lead Free Status: Lead Free; MFR_LIFECYCLE: Active; Manufacturer: Murata; Manufacturer Part Num: GRM1555C1H180JZ01D; Num Pins: 2; PART_SUBCLASS: CAPACITORS; RoHS Compliant: Yes; Temperature Coefficient: C0G; Voltage: 50V
FB27-FB29 FB37-FB40 = BEAD_FERRITE_SM: FERRITE BEAD 220 OHM 0402 1LN; Item Num: A51464-023; LIFECYCLE_PHASE: Active; MFR_LIFECYCLE: Active; Manufacturer: Murata; Manufacturer Part Num: BLM15AX221SN1D; Num Pins: 2; Part Class: Inductors; RoHS Compliant: Yes
R266-R272 R274 R279 R281 R284-R287 R293 R295 R298-R301 R303 R305 R315 R317 R320-R325 = RESISTOR: RES,1.00K OHMS,1.0%,1/16W,0402; Item Num: G60609-021; Lead Free Status: Yes; Manufacturer: Panasonic; Manufacturer Part Num: ERJ-2RKF1001X; Num Pins: 2; Part Class: Resistors; Tolerance: 1%
R273 R275-R278 R280 = RESISTOR: RES SMD 33 OHM 1% 1/16W 0402; Item Num: A93548-503; Lead Free Status: No; Manufacturer: Yageo; Manufacturer Part Num: RC0402FR-0733RL; Num Pins: 2; Part Class: Resistors; TOLERANCE: 1%
R282 R283 R337-R339 R341-R344 R346-R349 R351 R353 = RESISTOR: RES ZERO OHM 1/16W 5% 0402 SMD; Item Num: A93549-001; Lead Free Status: No; Manufacturer: Yageo; Manufacturer Part Num: RC0402JR-070RL; Num Pins: 2; Part Class: RESISTORS; RoHS Compliant: Yes; Tolerance: 5%
R292 R294 R314 R316 = RESISTOR: RES SMD 49.9 OHM 1% 1/10W 0402; AGILE_LINK: http://sj-agile9app/Agile/PLMServlet?action=OpenEmailObject&classid=10000&objid=146548997; Item Num: K16545-001; LIFECYCLE_PHASE: Active; Lead Free Status: Yes; MFR_LIFECYCLE: Active; Manufacturer: NIC Components Corp.; Manufacturer Part Num: NRC04F49R9TRF; Num Pins: 2; PART_SUBCLASS: RESISTORS; POWER: 1/16W; Part Class: Resistors; RoHS Compliant: Yes; TOLERANCE: 1%
R296 R297 R318 R319 R753 R754 = RESISTOR: RES SMD 49.9 OHM 1% 1/10W 0402; AGILE_LINK: http://sj-agile9app/Agile/PLMServlet?action=OpenEmailObject&classid=10000&objid=146548997; Item Num: K16545-001; LIFECYCLE_PHASE: Active; Lead Free Status: Yes; MFR_LIFECYCLE: Active; Manufacturer: NIC Components Corp.; Manufacturer Part Num: NRC04F49R9TRF; Num Pins: 2; PART_SUBCLASS: RESISTORS; POWER: 1/16W; Part Class: Resistors; RESISTANCE: 49.9; RoHS Compliant: Yes; TOLERANCE: 1%
SW4 = SPST4: SWITCHES - 4 POS, 8 PIN, Ultra-mini SMT Half-pitch Slider DIP Switch; Item Num: K15518-001; Lead Free Status: Yes; Manufacturer: C & K Components/ITT Industries; Num Pins: 8; Part Class: Switches; Price: 0; RoHS Compliant: Yes; Supplier: 8
U25 = Si52204: IC,CLK_GEN,32,QFN,N/A,GNRTR,PLL,; IPN: K21260-016; Item Num: K21260-016; Manufacturer: Silicon Labs Inc.; Manufacturer Part Num: SI52204-A01BGMR
U26 U27 = Si53254A-D02AM: IC,CLK_DRVR,40QFN,N/A,BUF,NON-PLL; Item Num: M28860-002; Manufacturer: Silabs; Manufacturer Part Num: SI53254A-D02AM
Y1 = CRYSTAL_SM_13: CRYSTAL - MINI XTL, 25.00MHZ, FREQ +/-50PPM, RANGE +/-30PPM -20~70C, 18PF, 2.0MM X 1.6MM SMD; Item Num: K72195-001; Lead Free Status: Yes; MFR_LIFECYCLE: Active; Manufacturer: Epson Toyocom; Manufacturer Part Num: FA-128 25.0000MB-C; Num Pins: 4; RoHS Compliant: Yes
C450 C452 C453 C457-C459 = Cap,_NP,_0402: CAP, CERAMIC, 100pF, 0402, 5%, 50VDC, NPO; Item Num: K13768-001; Manufacturer: Murata; Manufacturer Part Num: GRM1555C1H101JA01D; Temperature Coefficient: NPO; Voltage: 50V
EU1 EU2 = MAX31730ATC: IC, MAX31730, 3-Ch Remote Temp Sensor; IPN: K87190-001; Item Num: K87190-001; Manufacturer: Maxim
Q2 Q3 = 2N3906_0: TRANS PNP 40V 200MA SC75 SOT416; Item Num: K13941-001; Manufacturer: On-Semi; Manufacturer Part Num: MMBT3906TT1G
R327 R328 R332 R333 = RESISTOR: RES,33.2 OHMS,1.0%,1/16W,0402; AGILE_LINK: http://sj-agile9app/Agile/PLMServlet?action=OpenEmailObject&classid=10000&objid=146932246; Item Num: J38619-001; LIFECYCLE_PHASE: Active; MFR_LIFECYCLE: Active; Manufacturer: Panasonic; Manufacturer Part Num: ERJ-2RKF33R2X; Num Pins: 2; PART_SUBCLASS: RESISTORS; POWER: 1/16W; RESISTANCE: 10; RoHS Compliant: RoHS Compliant; TOLERANCE: 1%
R352 = RESISTOR: RES - 6.81K OHM, 1/16W, 1%, 0402 SMD; AGILE_LINK: http://sj-agile9app/Agile/PLMServlet?action=OpenEmailObject&classid=10000&objid=146548997; Item Num: K15642-001; LIFECYCLE_PHASE: Active; Lead Free Status: Yes; MFR_LIFECYCLE: Active; Manufacturer: Vishay; Manufacturer Part Num: CRCW04026K81FKxx; Manufaturer: Vishay; Num Pins: 2; PART_SUBCLASS: RESISTORS; POWER: 1/16W; Part Class: RESISTORS; RoHS Compliant: Yes; TOLERANCE: 1%
R814 = RESISTOR: CHIP RESISTOR, 0402, 1%,51.1K OHM, 1/10W; AGILE_LINK: http://sj-agile9app/Agile/PLMServlet?action=OpenEmailObject&classid=10000&objid=146548997; Item Num: M58194-001; LIFECYCLE_PHASE: Active; Lead Free Status: Yes; MFR_LIFECYCLE: Active; Manufacturer: Panasonic; Manufacturer Part Num: ERJ-2RKF5112X; Num Pins: 2; PART_SUBCLASS: RESISTORS; POWER: 1/10W; RESISTANCE: 51.1K; RoHS Compliant: Yes; TOLERANCE: 1%
R815-R821 = RESISTOR: CHIP RESISTOR, 0402, 1%,51.1K OHM, 1/10W; AGILE_LINK: http://sj-agile9app/Agile/PLMServlet?action=OpenEmailObject&classid=10000&objid=146548997; Item Num: M58194-001; LIFECYCLE_PHASE: Active; Lead Free Status: Yes; MFR_LIFECYCLE: Active; Manufacturer: Panasonic; Manufacturer Part Num: ERJ-2RKF5112X; Num Pins: 2; PART_SUBCLASS: RESISTORS; POWER: 1/10W; RoHS Compliant: Yes; TOLERANCE: 1%
U28 U31 = SN74LVC2G17DCKR: IC - Dual Schmitt-Trigger Buffer; Agile IPN: P01-18210R; IPN: K21749-001; Item Num: K21749-001; Manufacturer: Texas Instruments
U33 = MAX3002EUP+T: IC TRNSLTR BIDIRECTIONAL 20TSSOP; IPN: G13285-001; Item Num: G13285-001; Manufacturer: Texa Instrument
U87 U88 = NLSX4014MUTAG: IC, LEVEL TRANSLATOR; Item Num: M59362-001; Manufacturer: ON-SEMI

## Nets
1V8_SI53254_1: C420.2 C421.2 C422.2 C423.2 C424.2 C993.1 C994.1 C995.1 C996.1 C997.1 FB28.2 U26.1(VDD_DIG) U26.4(VDD) U26.9(VDDA) U26.15(VDDO0) U26.18(VDDO1)
1V8_SI53254_2: C432.2 C433.2 C434.2 C435.2 C436.2 C998.1 C999.1 C1000.1 C1001.1 C1002.1 FB29.2 U27.1(VDD_DIG) U27.4(VDD) U27.9(VDDA) U27.15(VDDO0) U27.18(VDDO1)
3V3_STBY: C451.2 C456.2 C460.2 C1018.2 C1021.2 EU1.1(VDD) EU2.1(VDD) R241.2 R242.2 R243.2 R244.2 R245.2 R246.2 R263.2 R264.2 R326.1 R331.1 R340.2 R345.2 R739.1 R808.2 U33.19(VCC) U87.11(VCC) U88.11(VCC) ; also on sheet 8 10 16 22 28 36 37 38 40 41 48 49 50 51 52 53 54 58
3V3_SYS: C344.1 C345.2 C351.2 C358.2 C364.2 C366.2 C370.2 C379.2 C380.2 C386.2 C395.2 C400.2 C403.2 C406.2 C409.2 C444.1 C449.1 C982.1 FB12.2 FB13.2 FB14.2 FB15.2 FB16.2 FB17.2 FB19.2 FB20.2 FB21.2 FB22.2 FB23.2 FB24.2 FB25.2 FB26.2 FB41.1 R744.1 R789.2 U22.14(VCC) U28.5(VCC) U31.5(VCC) U81.7(EN) U81.9(VIN1) U81.10(VIN2) ; also on sheet 29 30 35 36 37 41
GND: C344.2 C345.1 C346.1 C351.1 C352.1 C353.1 C354.1 C355.1 C356.1 C357.1 C358.1 C359.1 C360.1 C361.1 C362.1 C363.1 C364.1 C365.1 C366.1 C367.1 C368.1 C369.1 C370.1 C371.1 C372.1 C373.1 C374.1 C375.1 C376.1 C377.1 C378.1 C379.1 C380.1 C381.1 C382.1 C383.1 C384.1 C385.1 C386.1 C394.1 C395.1 C397.1 C398.1 C399.1 C400.1 C401.1 C402.1 C403.1 C404.1 C405.1 C406.1 C407.1 C408.1 C409.1 C410.2 C411.2 C412.1 C413.1 C414.1 C415.2 C416.2 C417.2 C418.2 C420.1 C421.1 C422.1 C423.1 C424.1 C432.1 C433.1 C434.1 C435.1 C436.1 C444.2 C449.2 C451.1 C456.1 C460.1 C461.1 C982.2 C984.1 C985.1 C986.1 C987.2 C988.1 C989.1 C990.2 C991.2 C992.2 C993.2 C994.2 C995.2 C996.2 C997.2 C998.2 C999.2 C1000.2 C1001.2 C1002.2 C1018.1 C1019.2 C1020.2 C1021.1 C1031.2 C1194.2 C1195.2 C1196.2 C1197.1 C1198.2 C1199.1 EU1.8(GND) EU1.13(GND_EP) EU2.8(GND) EU2.13(GND_EP) J9.A1(GND) J9.A4(GND) J9.A7(GND) J9.A10(GND) J9.A13(GND) J9.A16(GND) J9.A19(GND) J9.A22(GND) J9.A25(GND) J9.A28(GND) J9.A31(GND) J9.A34(GND) J9.A37(GND) J9.B1(GND) J9.B4(GND) J9.B7(GND) J9.B10(GND) J9.B13(GND) J9.B16(GND) J9.B19(GND) J9.B22(GND) J9.B25(GND) J9.B28(GND) J9.B31(GND) J9.B34(GND) J9.B37(GND) J9.MH1 J9.MH2 J9.MH3 J9.MH4 Q2.3(COLLECTOR) Q3.3(COLLECTOR) R234.2 R235.2 R236.2 R237.2 R239.1 R256.1 R257.1 R258.1 R259.1 R260.1 R261.1 R262.1 R265.2 R267.2 R269.2 R270.2 R274.2 R281.2 R285.2 R287.2 R292.1 R294.1 R295.2 R296.1 R297.1 R299.2 R301.2 R307.1 R308.1 R309.1 R314.1 R316.1 R317.2 R318.1 R319.1 R321.2 R323.2 R334.2 R343.1 R352.2 R359.1 R746.2 R753.1 R754.1 R815.1 R816.1 R817.1 R818.1 U22.7(GND) U23.65(EPAD) U24.2(GND) U25.8(VSSR) U25.32(GNDA) U25.33(GND_PAD) U26.11(GND1) U26.12(GND2) U26.41(GND_PAD) U27.11(GND1) U27.12(GND2) U27.41(GND_PAD) U28.2(GND) U31.2(GND) U33.11(GND) U81.5(GND) U81.11(EPAD) U87.6(GND) U88.6(GND) X1.4(GND) X2.4(GND) X2.5(GND) X2.10(GND) Y1.2 Y1.4 ; also on sheet 8 9 10 11 12 13 15 16 19 20 21 22 23 24 25 26 27 28 29 30 35 36 37 38 39 40 41 42 43 44 45 46 47 48 49 50 51 52 53 54 55 56 58
VDD18_ZL30733: C371.2 C372.2 C373.2 C374.2 C375.2 FB18.1 U23.1(VDD18) U23.2(VDD18) U23.15(VDD18) U23.37(VDD18)
VDD33_ZL30733: C361.2 C362.2 C367.2 C368.2 C369.2 FB17.1 U23.3(VDD33) U23.14(VDD33) U23.38(VDD33) U23.43(VDD33)
VDD_ZL_OSC: C381.2 C382.2 C383.2 FB20.1 R238.2 U24.4(VDD)
VDDIO_ZL30733: C359.2 C363.2 FB16.1 U23.44(VDDIO)
VDDO0_ZL30733: C353.2 C354.2 C355.2 FB13.1 FB42.1 U23.50(VDDO0)
VDDO1_ZL30733: C356.2 C357.2 FB14.1 U23.53(VDDO1)
VDDO2_ZL30733: C360.2 C365.2 FB15.1 U23.56(VDDO2)
VDDO3_ZL30733: C377.2 C378.2 FB19.1 U23.59(VDDO3)
VDDO4_ZL30733: C384.2 C385.2 FB21.1 U23.62(VDDO4)
VDDO5_ZL30733: C394.2 C397.2 FB22.1 U23.19(VDDO5)
VDDO6_ZL30733: C398.2 C399.2 FB23.1 U23.22(VDDO6)
VDDO7_ZL30733: C401.2 C402.2 FB24.1 U23.25(VDDO7)
VDDO8_ZL30733: C404.2 C405.2 FB25.1 U23.28(VDDO8)
VDDO9_ZL30733: C407.2 C408.2 FB26.1 U23.31(VDDO9)
BMC_BUF_TCK: R332.1 ; also on sheet 10
BMC_BUF_TDI: R333.1 ; also on sheet 10
BMC_BUF_TDO: U28.3(IN_2A) ; also on sheet 10
BMC_BUF_TMS: R327.1 ; also on sheet 10
BUF1_Q0_N: R289.2 U26.13(OUT0b)
BUF1_Q0_P: R288.2 U26.14(OUT0)
BUF1_Q1_N: R291.2 U26.16(OUT1b)
BUF1_Q1_P: R290.2 U26.17(OUT1)
BUF2_Q0_N: R311.2 U27.13(OUT0b)
BUF2_Q0_P: R310.2 U27.14(OUT0)
BUF2_Q1_N: R313.1 U27.16(OUT1b)
BUF2_Q1_P: R312.1 U27.17(OUT1)
BUFF1_IMP_SEL: R293.1 R295.1 U26.19(IMP_SEL)
BUFF1_OE0N: R298.1 R299.1 U26.31(OEb_OUT0)
BUFF1_OE1N: R300.1 R301.1 U26.32(OEb_OUT1)
BUFF1_OE2N: R303.1 U26.36(OEb_OUT2)
BUFF1_OE3N: R305.1 U26.37(OEb_OUT3)
BUFF2_IMP_SEL: R315.1 R317.1 U27.19(IMP_SEL)
BUFF2_OE0N: R320.1 R321.1 U27.31(OEb_OUT0)
BUFF2_OE1N: R322.1 R323.1 U27.32(OEb_OUT1)
BUFF2_OE2N: R324.1 U27.36(OEb_OUT2)
BUFF2_OE3N: R325.1 U27.37(OEb_OUT3)
C_PTP_SAMPLE_CLK_250M_N: C390.1 R748.1 U23.24(OUT7N)
C_PTP_SAMPLE_CLK_250M_P: C389.1 R748.2 U23.23(OUT7P)
C_QSFP_REFCLK_N: C396.1 R750.1 U23.21(OUT6N)
C_QSFP_REFCLK_P: C393.1 R750.2 U23.20(OUT6P)
C_QSFPDD_REFCLK_N: C392.1 R749.1 U23.18(OUT5N)
C_QSFPDD_REFCLK_P: C391.1 R749.2 U23.17(OUT5P)
C_ToD_MASTER_CLK_125M_N: C388.1 R747.1 U23.54(OUT1N)
C_ToD_MASTER_CLK_125M_P: C387.1 R747.2 U23.55(OUT1P)
CIPRI_HIGH_REFCLK_N: C1030.2 ; also on sheet 20
CIPRI_HIGH_REFCLK_P: C1029.2 ; also on sheet 20
CIPRI_LOW_REFCLK_N: C1028.2 ; also on sheet 20
CIPRI_LOW_REFCLK_P: C1027.2 ; also on sheet 20
CLK_100M_CXL_CONN_C_N: J9.B12(CLK0_DN) R226.1
CLK_100M_CXL_CONN_C_P: J9.B11(CLK0_DP) R225.1
CLK_CXL_CONN_N: R226.2 R316.2 U27.3(CLK_IN1b)
CLK_CXL_CONN_P: R225.2 R314.2 U27.2(CLK_IN1)
CLK_CXL_EP_N: R277.1 R319.2 U27.8(CLK_IN2b)
CLK_CXL_EP_P: R276.1 R318.2 U27.7(CLK_IN2)
CLK_FPGA_100M_N: R254.1 ; also on sheet 13
CLK_FPGA_100M_P: R253.1 ; also on sheet 13
CLK_REF4P: R6837.2 U23.4(REF4P)
CPU_1V2_RESETn: R819.1 U88.2(IO_VL1) ; also on sheet 16
CPU_RESETn: U88.10(IO_VCC1) ; also on sheet 10 36
CXL_PERSTn: J9.A11(PERST0_N) R227.1 R358.2 ; also on sheet 22 36
CXL_PERSTx1_N: J9.A29(PERST1_N) R227.2
CXL_PRSNTx4_N: J9.A12(PRSNT0_N) R789.1 U22.13(IOVCC1)
CXL_RX_N0: J9.A3(RX0_0N) ; also on sheet 20
CXL_RX_N1: J9.A6(RX0_1N) ; also on sheet 20
CXL_RX_N2: J9.A15(RX0_2N) ; also on sheet 20
CXL_RX_N3: J9.A18(RX0_3N) ; also on sheet 20
CXL_RX_P0: J9.A2(RX0_0P) ; also on sheet 20
CXL_RX_P1: J9.A5(RX0_1P) ; also on sheet 20
CXL_RX_P2: J9.A14(RX0_2P) ; also on sheet 20
CXL_RX_P3: J9.A17(RX0_3P) ; also on sheet 20
CXL_TX_C_N0: C341.2 J9.B3(TX0_0N)
CXL_TX_C_N1: C343.2 J9.B6(TX0_1N)
CXL_TX_C_N2: C348.2 J9.B15(TX0_2N)
CXL_TX_C_N3: C350.2 J9.B18(TX0_3N)
CXL_TX_C_P0: C340.2 J9.B2(TX0_0P)
CXL_TX_C_P1: C342.2 J9.B5(TX0_1P)
CXL_TX_C_P2: C347.2 J9.B14(TX0_2P)
CXL_TX_C_P3: C349.2 J9.B17(TX0_3P)
CXL_TX_N0: C341.1 ; also on sheet 20
CXL_TX_N1: C343.1 ; also on sheet 20
CXL_TX_N2: C348.1 ; also on sheet 20
CXL_TX_N3: C350.1 ; also on sheet 20
CXL_TX_P0: C340.1 ; also on sheet 20
CXL_TX_P1: C342.1 ; also on sheet 20
CXL_TX_P2: C347.1 ; also on sheet 20
CXL_TX_P3: C349.1 ; also on sheet 20
DDR4_COMP_REFCLK_N: R252.1 ; also on sheet 19
DDR4_COMP_REFCLK_P: R251.1 ; also on sheet 19
DDR4_DIMM1_REFCLK_N: R248.1 ; also on sheet 12
DDR4_DIMM1_REFCLK_P: R247.1 ; also on sheet 12
DDR4_DIMM2_REFCLK_N: R250.1 ; also on sheet 15
DDR4_DIMM2_REFCLK_P: R249.1 ; also on sheet 15
FPGA_1V2_LED0: R818.2 U87.2(IO_VL1) ; also on sheet 16
FPGA_1V2_LED1: R817.2 U87.3(IO_VL2) ; also on sheet 16
FPGA_1V2_LED2: R816.2 U87.4(IO_VL3) ; also on sheet 16
FPGA_1V2_LED3: R815.2 U87.5(IO_VL4) ; also on sheet 16
FPGA_3V3_LED0: U87.10(IO_VCC1) ; also on sheet 36
FPGA_3V3_LED1: U87.9(IO_VCC2) ; also on sheet 36
FPGA_3V3_LED2: U87.8(IO_VCC3) ; also on sheet 36
FPGA_3V3_LED3: U87.7(IO_VCC4) ; also on sheet 36
FPGA_CXL_PRSNTx4_N: R786.1 U22.2(IOVL1) ; also on sheet 16
FPGA_CXL_RSTn: R820.1 U88.3(IO_VL2) ; also on sheet 16
FPGA_RCVD_CLK1_REFOUT_N: C1009.1 R232.1 ; also on sheet 20
FPGA_RCVD_CLK1_REFOUT_P: C1008.1 R232.2 ; also on sheet 20
FPGA_RCVD_CLK2_REFOUT_N: C1011.1 R233.1 ; also on sheet 20
FPGA_RCVD_CLK2_REFOUT_P: C1010.1 R233.2 ; also on sheet 20
FPGA_TEMP0An: R338.2 ; also on sheet 11
FPGA_TEMP0Ap: R337.2 ; also on sheet 11
FPGA_TEMP3n: R341.2 ; also on sheet 22
FPGA_TEMP3p: R339.2 ; also on sheet 22
FPGA_TEMP4n: R344.2 ; also on sheet 22
FPGA_TEMP4p: R342.2 ; also on sheet 22
FPGA_TEMPDIODE0CN: R347.2 ; also on sheet 22
FPGA_TEMPDIODE0CP: R346.2 ; also on sheet 22
FPGA_VCCIO_1V2: C346.2 C1019.1 C1020.1 R786.2 R814.2 R819.2 R820.2 R821.2 U22.1(VL) U22.8(TSn) U87.1(VL) U87.12(EN) U88.1(VL) U88.12(EN) ; also on sheet 10 16 23 25 26 27 35 36 39 50 54 55 56
FPGA_VCCIO_SDM_HPS: FB27.1 FB28.1 FB29.1 FB37.1 FB38.1 FB39.1 FB40.1 R266.2 R268.2 R271.2 R272.2 R279.2 R284.2 R286.2 R293.2 R298.2 R300.2 R302.1 R303.2 R304.1 R305.2 R306.1 R315.2 R320.2 R322.2 R324.2 R325.2 SW4.8(B1) ; also on sheet 11 23 28 35 39 52 53
GPIO0_3V3_AC0_ZL_INT_N: R242.1 R258.2 U23.49(GPIO0_AC0) ; also on sheet 10
GPIO1_3V3_AC1_PTP_CLK_LOL: R243.1 R259.2 U23.48(GPIO1_AC1) ; also on sheet 10
GPIO2_1V2_AC2_FPGA_HPS_ZL_HO: R814.1 U88.5(IO_VL4) ; also on sheet 10
GPIO2_3V3_AC2_FPGA_HPS_ZL_HO: R244.1 R260.2 U23.47(GPIO2_AC2) U88.7(IO_VCC4)
GPIO4_AC4: R246.1 R262.2 U23.45(GPIO4_AC4)
GXF_1V2_2ND_PERSTn: R821.1 U88.4(IO_VL3) ; also on sheet 16
GXF_2ND_PERSTn: U33.6(IO_VL5) ; also on sheet 10 22 36
GXF_3V3_2ND_PERSTn: R808.1 U33.15(IO_VCC5) U88.8(IO_VCC3)
INLET_TEMP_N: Q2.2(BASE) R349.2
INLET_TEMP_P: Q2.1(EMITTER) R348.2
LT_1V8_SCK: U33.1(IO_VL1) ; also on sheet 10
LT_1V8_SCSn: R737.1 U33.5(IO_VL4) ; also on sheet 10
LT_1V8_SDI: U33.3(IO_VL2) ; also on sheet 10
LT_1V8_SPI_ERRn: R768.1 U33.4(IO_VL3) ; also on sheet 10
LT_3V3_SCK: U33.20(IO_VCC1) ; also on sheet 42
LT_3V3_SCSn: U33.16(IO_VCC4) ; also on sheet 42
LT_3V3_SDI: U33.18(IO_VCC2) ; also on sheet 42
LT_3V3_SPI_ERRn: U33.17(IO_VCC3) ; also on sheet 42
MAX_1V8: C461.2 R359.2 R737.2 R768.2 U33.2(VL) U33.10(EN) ; also on sheet 9 10 11 58
MAX_I2C_SCL: EU1.12(SCL) EU2.12(SCL) R263.1 R282.1 U23.36(SCK_SCL) ; also on sheet 8 10 37 40 42 49 50
MAX_I2C_SDA: EU1.11(SDA) EU2.11(SDA) R264.1 R283.1 U23.35(SI_SDA) ; also on sheet 8 10 37 40 42 49 50
OUTLET_TEMP_N: Q3.2(BASE) R353.2
OUTLET_TEMP_P: Q3.1(EMITTER) R351.2
PCIE_EP_JTAG_TCK: R334.1 U31.1(IN_1A) ; also on sheet 8
PCIE_EP_JTAG_TDI: R331.2 U31.3(IN_2A) ; also on sheet 8
PCIE_EP_JTAG_TDO: R328.1 ; also on sheet 8
PCIE_EP_JTAG_TMS: R326.2 U28.1(IN_1A) ; also on sheet 8
PG_ZL70733_1V8: R744.2 U81.4(POK)
PPS_FPGA_CLKOUT: U23.8(REF2P) ; also on sheet 16
PTP_CLK_RST_N: R265.1 R739.2 U23.16(RST_B) ; also on sheet 10
PTP_SAMPLE_CLK_250M_N: C390.2 ; also on sheet 16
PTP_SAMPLE_CLK_250M_P: C389.2 ; also on sheet 16
QSFP_REFCLK_N: C396.2 ; also on sheet 20
QSFP_REFCLK_P: C393.2 ; also on sheet 20
QSFPDD_REFCLK_N: C392.2 ; also on sheet 20
QSFPDD_REFCLK_P: C391.2 ; also on sheet 20
R_CIPRI_HIGH_REFCLK_N: C1030.1 R842.1 U23.27(OUT8N)
R_CIPRI_HIGH_REFCLK_P: C1029.1 R842.2 U23.26(OUT8P)
R_CIPRI_LOW_REFCLK_N: C1028.1 R843.1 U23.30(OUT9N)
R_CIPRI_LOW_REFCLK_P: C1027.1 R843.2 U23.29(OUT9P)
R_CLK_FPGA_100M_N: R254.2 R6940.1 U23.51(OUT0N)
R_CLK_FPGA_100M_P: R253.2 R6940.2 U23.52(OUT0P)
R_DDR4_COMP_REFCLK_N: R252.2 R6943.1 U23.63(OUT4N)
R_DDR4_COMP_REFCLK_P: R251.2 R6943.2 U23.64(OUT4P)
R_DDR4_DIMM1_REFCLK_N: R248.2 R6941.1 U23.57(OUT2N)
R_DDR4_DIMM1_REFCLK_P: R247.2 R6941.2 U23.58(OUT2P)
R_DDR4_DIMM2_REFCLK_N: R250.2 R6942.1 U23.60(OUT3N)
R_DDR4_DIMM2_REFCLK_P: R249.2 R6942.2 U23.61(OUT3P)
REFCLK_CXL_CONN_N: R311.1 ; also on sheet 20
REFCLK_CXL_CONN_P: R310.1 ; also on sheet 20
REFCLK_CXL_EP_N: R313.2 ; also on sheet 20
REFCLK_CXL_EP_P: R312.2 ; also on sheet 20
REFCLK_CXL_RP_N: J9.B30(CLK1_DN) R280.1 R754.2
REFCLK_CXL_RP_P: J9.B29(CLK1_DP) R278.1 R753.2
REFCLK_PCIE_13A_CH2_N: R291.1 ; also on sheet 21
REFCLK_PCIE_13A_CH2_P: R290.1 ; also on sheet 21
REFCLK_PCIE_13A_CH5_N: R289.1 ; also on sheet 21
REFCLK_PCIE_13A_CH5_P: R288.1 ; also on sheet 21
REFCLK_PCIE_EP_EDGE_N: R294.2 U26.3(CLK_IN1b) ; also on sheet 8
REFCLK_PCIE_EP_EDGE_P: R292.2 U26.2(CLK_IN1) ; also on sheet 8
REFCLK_PCIE_EP_N: R275.1 R297.2 U26.8(CLK_IN2b)
REFCLK_PCIE_EP_P: R273.1 R296.2 U26.7(CLK_IN2)
SEL_CXL_REFCLK: R302.2 SW4.2(A2) U27.20(CLK_SEL)
SEL_PCIE_REFCLK: R304.2 SW4.3(A3) U26.20(CLK_SEL)
SI2204_OUT0n: R275.2 U25.13(DIFF_0b)
SI2204_OUT0p: R273.2 U25.12(DIFF_0)
SI2204_OUT1n: R277.2 U25.18(DIFF_1b)
SI2204_OUT1p: R276.2 U25.17(DIFF_1)
SI2204_OUT2n: R280.2 U25.22(DIFF_2b)
SI2204_OUT2p: R278.2 U25.21(DIFF_2)
SI52204_FS: R284.1 R285.1 U25.11(FS)
SI52204_OE0n: R266.1 R267.1 U25.14(OE_0b)
SI52204_OE1n: R268.1 R270.1 U25.16(OE_1b)
SI52204_OE2n: R269.1 R271.1 U25.23(OE_2b)
SI52204_OE3n: R272.1 R274.1 U25.27(OE_3b)
SI52204_PWRDNB: R306.2 SW4.4(A4) U25.2(PWRGD/PWRDNb)
SI52204_SA: R286.1 R287.1 U25.7(REF/SA)
SI52204_SSEN: R279.1 R281.1 SW4.1(A1) U25.1(SS_EN)
TEMP1_THERMn: EU1.9(~{THERM}) R340.1 ; also on sheet 10
TEMP2_THERMn: EU2.9(~{THERM}) R345.1 ; also on sheet 10
ToD_MASTER_CLK_125M_N: C388.2 ; also on sheet 16
ToD_MASTER_CLK_125M_P: C387.2 ; also on sheet 16
ZL30733_1V8: C376.2 C983.2 C984.2 C985.2 C986.2 FB18.2 FB42.2 R745.2 U81.1(VOUT1) U81.2(VOUT2)
ZL_GPIO3_AC3: R245.1 R261.2 U23.46(GPIO3_AC3) ; also on sheet 10
ZL_OSC_CLK: R240.2 U23.39(OSCB)
N631911: C410.1 U25.3(XIN/CLKIN) Y1.3
N632203: C412.2 C415.1 C416.1 FB27.2 U25.19(VDD0) U25.29(VDD1)
N632477: C411.1 U25.4(XOUT) Y1.1
N632667: C989.2 C991.1 C992.1 FB40.2 U25.15(VDD_IO0) U25.24(VDD_IO1)
N633145: R282.2 U25.10(SCLK)
N633209: R283.2 U25.9(SDA)
N634717: R307.2 SW4.5(B4)
N634773: R308.2 SW4.6(B3)
N634823: R309.2 SW4.7(B2)
N754746: R327.2 U28.6(OUT_1Y)
N754798: R328.2 U28.4(OUT_2Y)
N754986: R332.2 U31.6(OUT_1Y)
N755042: R333.2 U31.4(OUT_2Y)
N760346: C450.2 EU1.3(DXN1) R338.1
N760350: C450.1 EU1.2(DXP1) R337.1
N760466: C452.2 EU1.5(DXN2) R341.1
N760470: C452.1 EU1.4(DXP2) R339.1
N760588: C453.2 EU1.7(DXN3) R344.1
N760592: C453.1 EU1.6(DXP3) R342.1
N760654: EU1.10(ADD) R343.2
N972002: C457.2 EU2.3(DXN1) R347.1
N972006: C457.1 EU2.2(DXP1) R346.1
N972122: C458.2 EU2.5(DXN2) R349.1
N972126: C458.1 EU2.4(DXP2) R348.1
N972244: C459.2 EU2.7(DXN3) R353.1
N972248: C459.1 EU2.6(DXP3) R351.1
N972310: EU2.10(ADD) R352.1
N1703298: C1008.2 R228.2 R237.1 U23.12(REF0P)
N1703311: C1009.2 R229.2 R234.1 U23.13(REF0N)
N1703324: C1010.2 R230.2 R235.1 U23.10(REF1P)
N1703337: C1011.2 R231.2 R236.1 U23.11(REF1N)
N1703797: C352.2 FB12.1 R228.1 R229.1 R230.1 R231.1
N1706943: R238.1 U24.1(EN)
N1707033: R240.1 U24.3(OUT)
N1707243: R239.2 U23.41(OSCI)
N1762439: R241.1 R256.2 U23.33(SO_IF1)
N1762443: R257.2 U23.34(CS_B_IF0)
N5238722: C983.1 R745.1 R746.1 U81.3(VFB)
N5238738: C987.1 U81.6(SS)
N5254399: C413.2 C417.1 FB37.2 U25.5(VDDX)
N5254403: C414.2 C418.1 FB38.2 U25.6(VDDR)
N5254415: C988.2 C990.1 FB39.2 U25.31(VDDA)
N5872472: R358.1 U88.9(IO_VCC2)
N6731924: C1031.1 C1194.1 C1195.1 C1196.1 C1197.2 C1198.1 FB41.2 X1.9(VCC33) X2.8(EN) X2.9(VDD33)
N6732170: C1199.2 X2.7(FILTER)
N6732230: R6837.1 X1.5(REFOUT) X2.6(REFOUT)

Not connected (* = marked no-connect by the designer): J9 A8(SMB0_SCL)* A9(SMB0_SDA)* A20(RX1_0P)* A21(RX1_0N)* A23(RX1_1P)* A24(RX1_1N)* A26(SMB1_SCL)* A27(SMB1_SDA)* A30(PRSNT1_N)* A32(RX1_2P)* A33(RX1_2N)* A35(RX1_3P)* A36(RX1_3N)* B8(NC)* B9(SMB0_ALERT_N)* B20(TX1_0P)* B21(TX1_0N)* B23(TX1_1P)* B24(TX1_1N)* B26(NC)* B27(SMB1_ALERT_N)* B32(TX1_2P)* B33(TX1_2N)* B35(TX1_3P)* B36(TX1_3N)*; U22 3(IOVL2)* 4(IOVL3)* 5(IOVL4)* 6(NC0)* 9(NC1)* 10(IOVCC4)* 11(IOVCC3)* 12(IOVCC2)*; U23 5(REF4N)* 6(REF3P)* 7(REF3N)* 9(REF2N)* 32(IC0)* 40(OSCO)* 42(OSCA)*; U25 20(NC0)* 25(DIFF_3)* 26(DIFF_3b)* 28(NC1)* 30(NC2)*; U26 5(NC1)* 6(NC2)* 10(LOS)* 21(OUT2b)* 22(OUT2)* 23(OUT3b)* 24(OUT3)* 25(VDDO2)* 26(NC3)* 27(NC4)* 28(NC5)* 29(NC6)* 30(NC7)* 33(NC8)* 34(NC9)* 35(NC10)* 38(NC11)* 39(NC12)* 40(NC13)*; U27 5(NC1)* 6(NC2)* 10(LOS)* 21(OUT2b)* 22(OUT2)* 23(OUT3b)* 24(OUT3)* 25(VDDO2)* 26(NC3)* 27(NC4)* 28(NC5)* 29(NC6)* 30(NC7)* 33(NC8)* 34(NC9)* 35(NC10)* 38(NC11)* 39(NC12)* 40(NC13)*; U33 7(IO_VL6)* 8(IO_VL7)* 9(IO_VL8)* 12(IO_VCC8)* 13(IO_VCC7)* 14(IO_VCC6)*; U81 8(NC)*; X1 1(NC)* 2(NC)* 3(DNC)* 6(NC)* 7(NC)* 8(NC)* 10(DNC/VC)*; X2 1(VC/NC)* 2(DNC)* 3(DNC)*

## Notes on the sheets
sheet 31
- CXL Connector
- 1.65V - 5.5V
- 1.2V - 5.5V
- Design Note:
  Clock for RootPort mode.
- CXL Interface is designed to support the FM85 Devkit M.2 Daughter Card (M-Key for
  PCIex4 and SATA).  When connecting to this card, FM86 Devkit CXL channels will be
  connected to M.2 channels 8-11 (J5) on the daughter card.  PCIE_100M_ROOT0_P/N clock
  must be selected as the default PCIE clock on the M.2 Daughter Card.
  For FM86 Devkit to FM86 Devkit communication using PCIEx4 over CXL with one devkit
  configured as the RP and the other as the EP, you must use the local PCIE CLK from U25
  (REFCLK_CXL_RP_P/N) for each board
  I2C is not supported.
sheet 32
- Clock 1
- Shared Footprint:
  Overlap one pad of
  each FB so only one
  can be installed
- VDDO0 can be 1.8V or 3.3V (Default).
  -When 3.3V, OUT0 Clock will be 100MHz LVDS
  FPGA Clock.
  -When 1.8V, OUT0 Clock can be changed to
  1.8V LVCMOS to drive 100MHz SE FPGA clock
  on the P leg and FPGA 1PPS Clock on the N
  leg.  For this case, the optional resistor
  dividers (R6840-R6843) should be installed
  to match the FPGA clock input 1.5V LVCMOS
  requirements).  See Agilex Datasheet.
- 1.8V to 3.3V +/-5%
- 156.25MHz
- 3.3V +/-5%
- 184.32MHz
- LVCMOS
- 1.8V +/-5%
- 1.8V to 3.3V +/-5%
- LVDS
- 100MHz
- PROG_DIFF
- 125MHz
- [GPIO0_AC0 : GPIO2_AC2] = 000 for pre-configuration
- LVDS
- 166.625MHz
  DDR4-2666
- LVDS
- 166.625MHz
  DDR4-2666
- LVDS
- 166.625MHz
  DDR4-2666
- PROG_DIFF
- 156.25MHz
- PROG_DIFF
- 156.25MHz
- PROG_DIFF
- 250MHz
- PROG_DIFF
- 184.32MHz
- I2C Mode
- PROG_DIFF
- 153.6MHz
- I2C_ADDR0 = 0
- Place close to OUTxP/N pins of ZL30733
- I2C:
  AbsMax = 3.6V
  Vih_min = 0.7 x VDDIO = 2.31V
  Vil_max = 0.3 x VDDIO = 0.99V
- GPIO3_AC3, GPIO4_AC4
  must be low at rising
  edge of RST_B
- I2C ADDR = 70H
- Optional TCXO or OCXO clock
  Install only one if used
- Vout = 0.5V x (Rup/Rdn + 1)
- VDOmax = 185mV
- 1.8V @ 367mA
- VINabsmax = -0.3V to 6.5V
- Rup
- Rdn
- ENth = 0.3V /0.8V / 1V
  ABSmax = 6.5V
- OVERLAP FOOTPRINT
sheet 33
- Clock 2
- Place one 0.1uF per VDDx pins
- VDD, VDDX, VDDA, VDDR, VDD_IO = 1.5V or 1.8V +/-5%
- Disable OE2n and
  OE3n by default
- Control Pins:
  AbsMax = VDDmax + 0.5V = 3.0V
  Vih_min = 0.75 x VDD = 1.35V
  Vil_max = 0.25 x VDD = 0.45V
- 100Mhz HCSL
- 100Mhz HCSL
- 100Mhz HCSL
- Pull-ups on PG35
- I2C:
  AbsMax = 3.6V
  Vih_min = 1.11V
  Vil_max = 0.6V
- ADDR = 6AH
- Push-Pull HCSL clock outputs
  Termination not needed
- FS      SS
   0      0.25% downspread
   Mid    OFF (Default)
   1      0.50% downspread
- FS      Freq
   0      100MHz (Default)
   Mid    200MHz
   1      133MHz
- Place one 0.1uF & 1uF per VDDx pins
- VDD, VDDA, VDD_DIG = 1.8V to 3.3V +/-5%
  VDDO = 1.8V, 2.5V, or 3.3V +/-5%
- CLK_SEL      Input
      0        CLKIN2
      1        CLKIN1
- SA      Address
   0       69H
   1       6AH  (Default)
- Control Pins:
  AbsMax = 1.1 x VDDmax = 3.81V
  Vih_min = 0.7 x VDD = 1.26V
  Vil_max = 0.3 x VDD = 0.54V
- Unpowered
  for Out2,3
- 100Mhz HCSL
- 100Mhz HCSL
- 100Mhz HCSL
- 100Mhz HCSL
- Termination provided on-chip
- Termination depends on off-board Clock
  Source and installed by default, assuming
  standard HCSL driver
- powered by
  VCCO2
- 85ohm
- powered by
  VCCO2
- Push-Pull Clock Source
  Termination not needed
- 100ohm (Default)
- SW4.2 to SW4.4:
  OPEN = HIGH
  CLOSE = LOW
- SW4.1 Open = No Sread Spectrum
  SW4.1 Close = 0.5% Down Spread
- Place one 0.1uF & 1uF per VDDx pins
- CLK_SEL      Input
      0        CLKIN2
      1        CLKIN1
- Control Pins:
  AbsMax = 1.1 x VDDmax = 3.81V
  Vih_min = 0.7 x VDD = 1.26V
  Vil_max = 0.3 x VDD = 0.54V
- Unpowered
  for Out2,3
- 100Mhz HCSL
- 100Mhz HCSL
- 100Mhz HCSL
- 100Mhz HCSL
- 85ohm
- Termination depends on off-board Clock
  Source and installed by default, assuming
  standard HCSL driver
- powered by
  VCCO2
- Termination provided on-chip
- 100ohm (Default)
- powered by
  VCCO2
- Push-Pull Clock Source
  Termination not needed
sheet 34
- VCC = 1.65V-5.5V
- VCC = 1.65V-5.5V
- From PCIe
- To MAX10
- From PCIe
- To MAX10
- To PCIE
- From MAX10
- From PCIe
- To MAX10
- Schmitt Buffer
- Schmitt Buffer
- VDD = 3V - 3.6V
- Core A
- F-TILE
   12C
- F-TILE
  13A
- I2C ADDR = 38
- Pull-ups on PG35
- I2C:
  AbsMax = 3.7V
  Vih_min = 2.2V
  Vil_max = 0.8V
- VDD = 3V - 3.6V
- Core C
- EN:
  VIH = 0.96V
  VIL = 0.24V
  Absmax = 5.5V
- Place at
  Inlet
- I2C ADDR = 9A
- Pull-ups on PG35
- I2C:
  AbsMax = 3.7V
  Vih_min = 2.2V
  Vil_max = 0.8V
- Place at
  Outlet
- Board Temp Sensor
- Route all DXPx/DXNx
  pairs as a diff pair
  and avoid other
  nearby signals
- 1.65V-5.5V
- 1.4V-3.6V
- Pull-up on pg46
- EN:
  VIH = 0.96V
  VIL = 0.24V
  Absmax = 5.5V
- EN:
  VIL = 0.63V
  VIH = 1.17V
- Internal pullup on each IO-VCC, IO-VL
  -4K when driving high
  -40K when driving low
